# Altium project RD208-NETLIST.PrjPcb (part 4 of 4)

## Sheet 8.SchDoc
size 609 x 444 mm
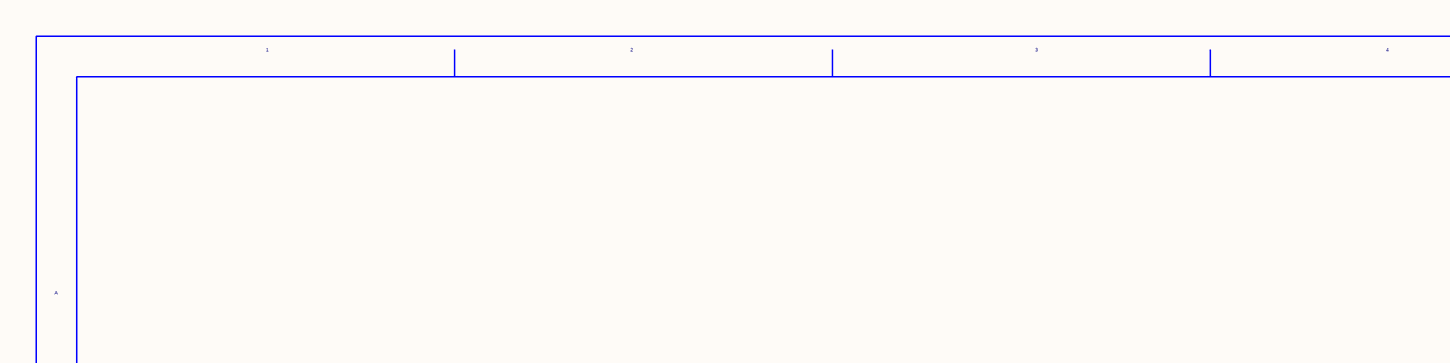
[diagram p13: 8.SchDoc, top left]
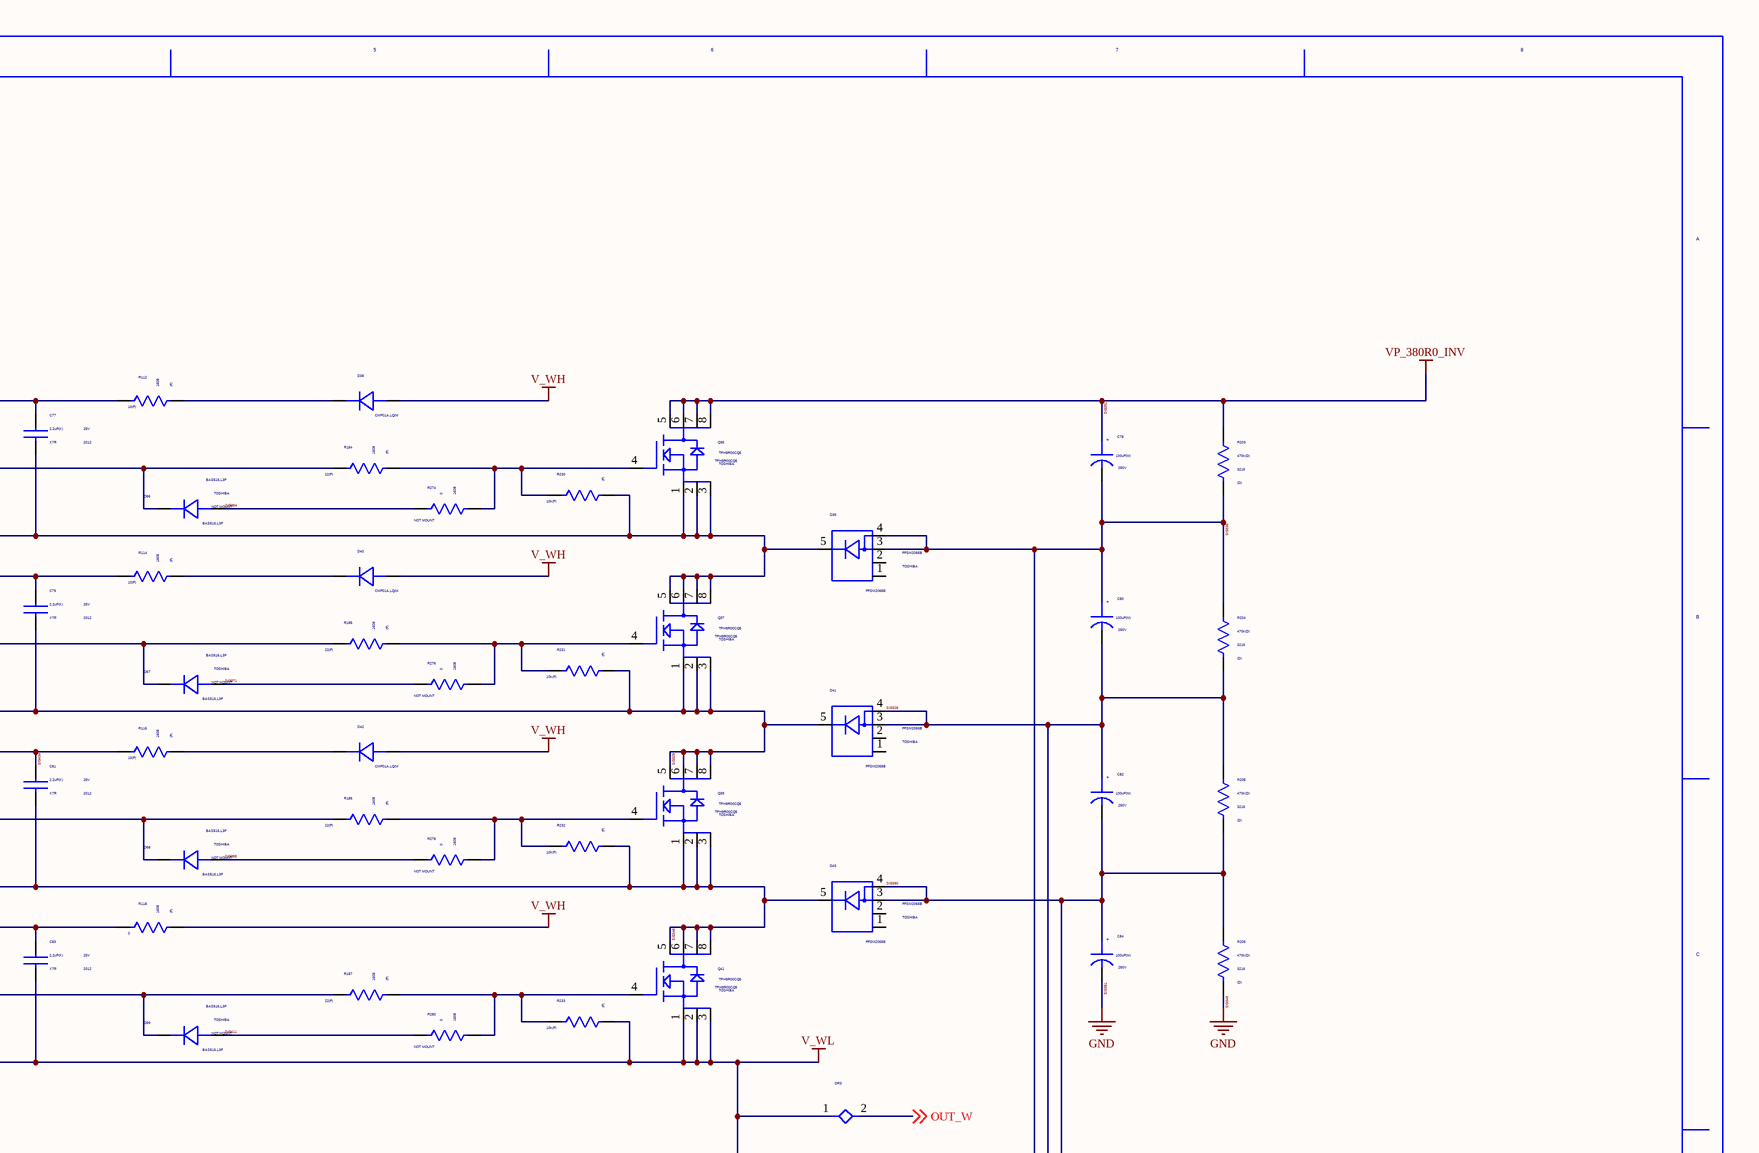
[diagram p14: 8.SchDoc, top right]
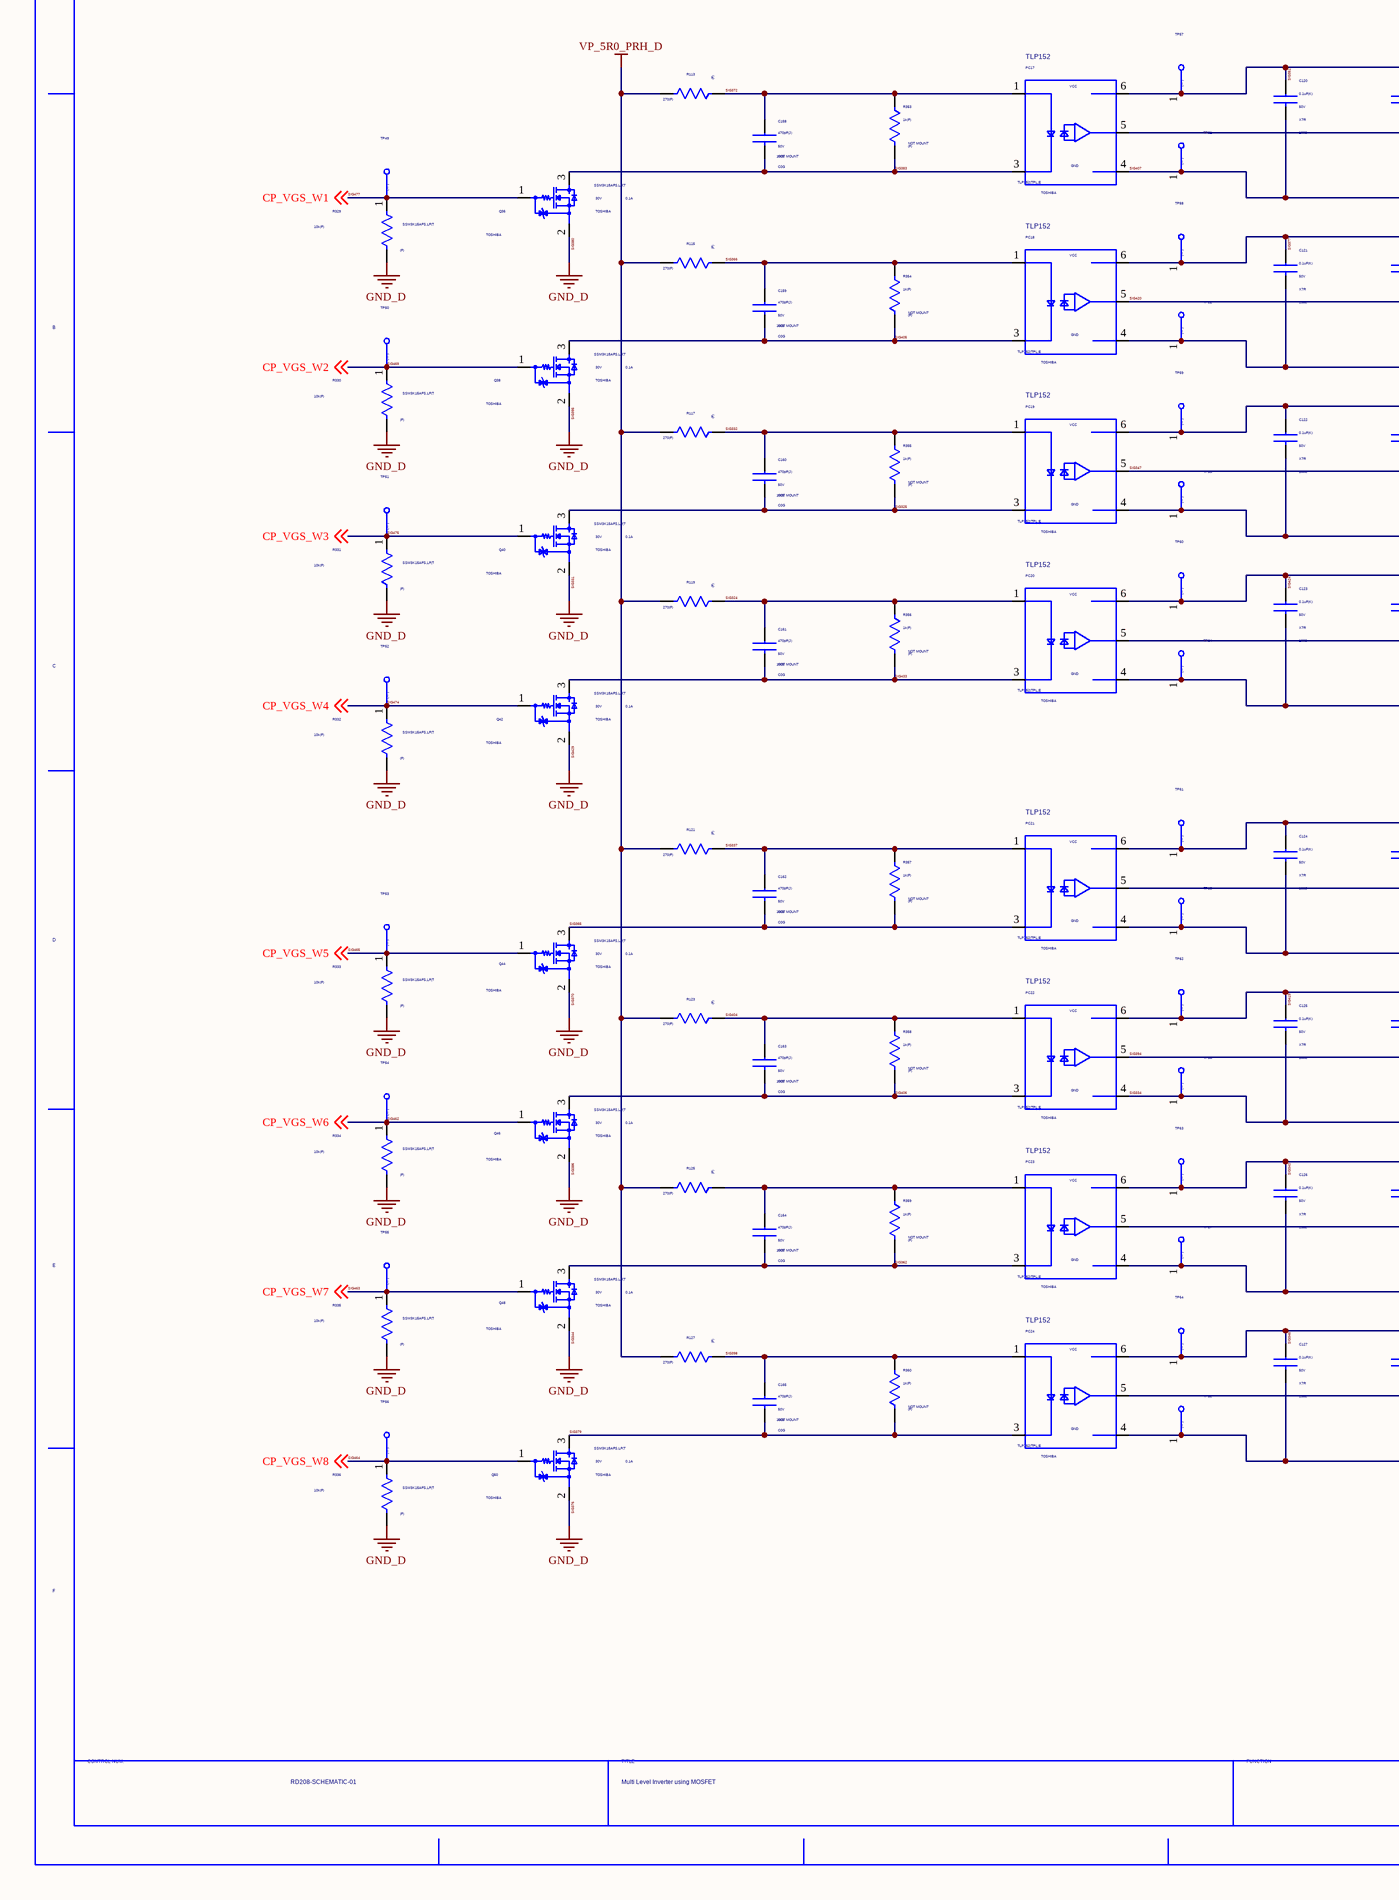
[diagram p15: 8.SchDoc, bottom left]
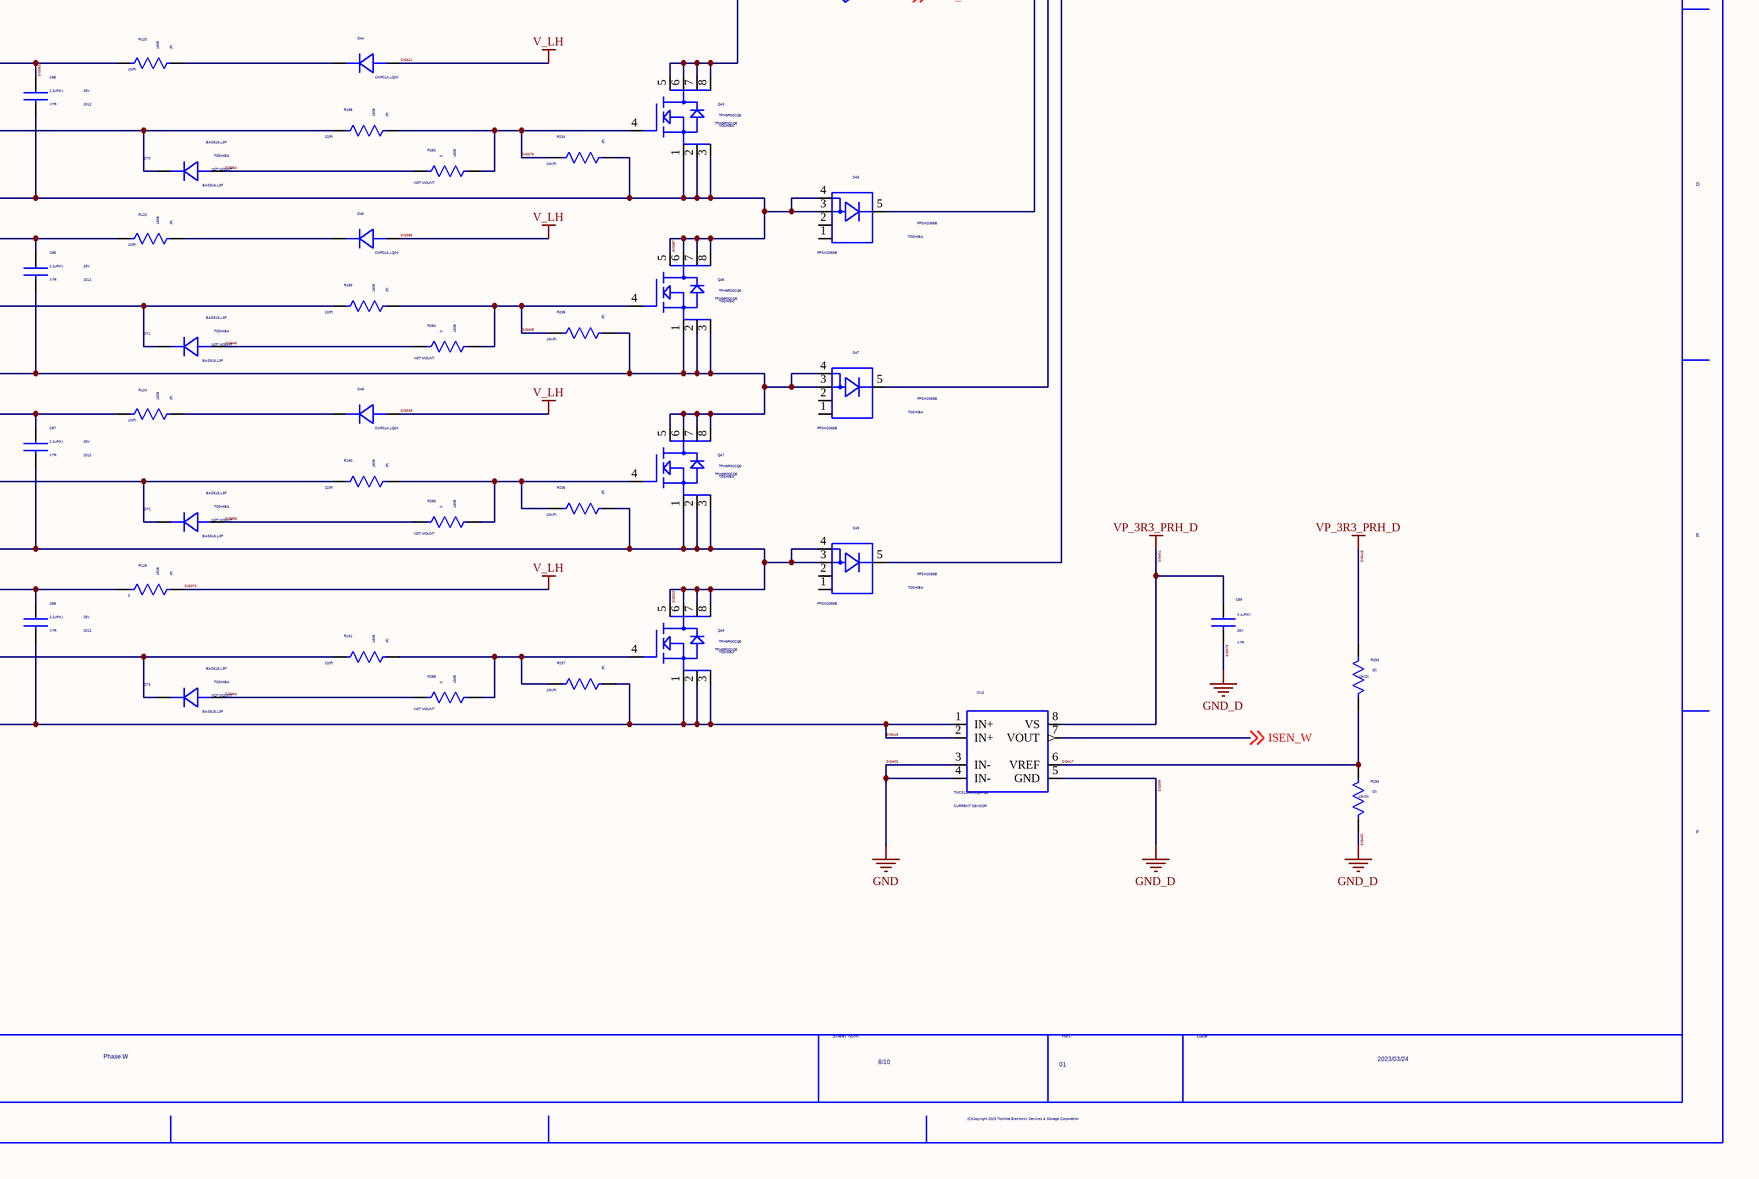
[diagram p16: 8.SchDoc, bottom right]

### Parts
(Parts that share a designator on the sheet are numbered #1, #2 ... from top to bottom, then left to right.)
C77  VAL2: 25V  SIZECODESMD: 2012  VALUE4: X7R  VAL1: 2.2uF(K)  (hidden comment: GRM21BR71E225KE11L)
C78  VAL2: 250V  VAL1: 100uF(M)  (hidden comment: EKMQ251ELL101ML25S)
C79  VAL2: 25V  SIZECODESMD: 2012  VALUE4: X7R  VAL1: 2.2uF(K)  (hidden comment: GRM21BR71E225KE11L)
C80  VAL2: 250V  VAL1: 100uF(M)  (hidden comment: EKMQ251ELL101ML25S)
C81  VAL2: 25V  SIZECODESMD: 2012  VALUE4: X7R  VAL1: 2.2uF(K)  (hidden comment: GRM21BR71E225KE11L)
C82  VAL2: 250V  VAL1: 100uF(M)  (hidden comment: EKMQ251ELL101ML25S)
C83  VAL2: 25V  SIZECODESMD: 2012  VALUE4: X7R  VAL1: 2.2uF(K)  (hidden comment: GRM21BR71E225KE11L)
C84  VAL2: 250V  VAL1: 100uF(M)  (hidden comment: EKMQ251ELL101ML25S)
C85  VAL2: 25V  SIZECODESMD: 2012  VALUE4: X7R  VAL1: 2.2uF(K)  (hidden comment: GRM21BR71E225KE11L)
C86  VAL2: 25V  SIZECODESMD: 2012  VALUE4: X7R  VAL1: 2.2uF(K)  (hidden comment: GRM21BR71E225KE11L)
C87  VAL2: 25V  SIZECODESMD: 2012  VALUE4: X7R  VAL1: 2.2uF(K)  (hidden comment: GRM21BR71E225KE11L)
C88  VAL2: 25V  SIZECODESMD: 2012  VALUE4: X7R  VAL1: 2.2uF(K)  (hidden comment: GRM21BR71E225KE11L)
C89  VAL2: 25V  VALUE4: X7R  VAL1: 0.1uF(K)  (hidden comment: GRM155R71E104KE14D)
C120  VAL2: 50V  SIZECODESMD: 1608  VALUE4: X7R  VAL1: 0.1uF(K)  (hidden comment: C1608X7R1H104K080AA)
C121  VAL2: 50V  SIZECODESMD: 1608  VALUE4: X7R  VAL1: 0.1uF(K)  (hidden comment: C1608X7R1H104K080AA)
C122  VAL2: 50V  SIZECODESMD: 1608  VALUE4: X7R  VAL1: 0.1uF(K)  (hidden comment: C1608X7R1H104K080AA)
C123  VAL2: 50V  SIZECODESMD: 1608  VALUE4: X7R  VAL1: 0.1uF(K)  (hidden comment: C1608X7R1H104K080AA)
C124  VAL2: 50V  SIZECODESMD: 1608  VALUE4: X7R  VAL1: 0.1uF(K)  (hidden comment: C1608X7R1H104K080AA)
C125  VAL2: 50V  SIZECODESMD: 1608  VALUE4: X7R  VAL1: 0.1uF(K)  (hidden comment: C1608X7R1H104K080AA)
C126  VAL2: 50V  SIZECODESMD: 1608  VALUE4: X7R  VAL1: 0.1uF(K)  (hidden comment: C1608X7R1H104K080AA)
C127  VAL2: 50V  SIZECODESMD: 1608  VALUE4: X7R  VAL1: 0.1uF(K)  (hidden comment: C1608X7R1H104K080AA)
C158  VAL2: 50V  SIZECODESMD: 1005  VALUE4: C0G  VAL1: 470pF(J)  NOTMOUNT: NOT MOUNT  (hidden comment: GRM1555C1H471JA01J)
C159  VAL2: 50V  SIZECODESMD: 1005  VALUE4: C0G  VAL1: 470pF(J)  NOTMOUNT: NOT MOUNT  (hidden comment: GRM1555C1H471JA01J)
C160  VAL2: 50V  SIZECODESMD: 1005  VALUE4: C0G  VAL1: 470pF(J)  NOTMOUNT: NOT MOUNT  (hidden comment: GRM1555C1H471JA01J)
C161  VAL2: 50V  SIZECODESMD: 1005  VALUE4: C0G  VAL1: 470pF(J)  NOTMOUNT: NOT MOUNT  (hidden comment: GRM1555C1H471JA01J)
C162  VAL2: 50V  SIZECODESMD: 1005  VALUE4: C0G  VAL1: 470pF(J)  NOTMOUNT: NOT MOUNT  (hidden comment: GRM1555C1H471JA01J)
C163  VAL2: 50V  SIZECODESMD: 1005  VALUE4: C0G  VAL1: 470pF(J)  NOTMOUNT: NOT MOUNT  (hidden comment: GRM1555C1H471JA01J)
C164  VAL2: 50V  SIZECODESMD: 1005  VALUE4: C0G  VAL1: 470pF(J)  NOTMOUNT: NOT MOUNT  (hidden comment: GRM1555C1H471JA01J)
C165  VAL2: 50V  SIZECODESMD: 1005  VALUE4: C0G  VAL1: 470pF(J)  NOTMOUNT: NOT MOUNT  (hidden comment: GRM1555C1H471JA01J)
D38  VAL1: CMF01A,LQ(M  (hidden comment: CMF01A,LQ_M)
D39  USERCOMPTEXT3: TOSHIBA  (hidden comment: FFSM2065B)
D40  VAL1: CMF01A,LQ(M  (hidden comment: CMF01A,LQ_M)
D41  USERCOMPTEXT3: TOSHIBA  (hidden comment: FFSM2065B)
D42  VAL1: CMF01A,LQ(M  (hidden comment: CMF01A,LQ_M)
D43  USERCOMPTEXT3: TOSHIBA  (hidden comment: FFSM2065B)
D44  VAL1: CMF01A,LQ(M  (hidden comment: CMF01A,LQ_M)
D45  USERCOMPTEXT3: TOSHIBA  (hidden comment: FFSM2065B)
D46  VAL1: CMF01A,LQ(M  (hidden comment: CMF01A,LQ_M)
D47  USERCOMPTEXT3: TOSHIBA  (hidden comment: FFSM2065B)
D48  VAL1: CMF01A,LQ(M  (hidden comment: CMF01A,LQ_M)
D49  USERCOMPTEXT3: TOSHIBA  (hidden comment: FFSM2065B)
D66  USERCOMPTEXT3: TOSHIBA  NOTMOUNT: NOT MOUNT  (hidden comment: BAS516,L3F)
D67  USERCOMPTEXT3: TOSHIBA  NOTMOUNT: NOT MOUNT  (hidden comment: BAS516,L3F)
D68  USERCOMPTEXT3: TOSHIBA  NOTMOUNT: NOT MOUNT  (hidden comment: BAS516,L3F)
D69  USERCOMPTEXT3: TOSHIBA  NOTMOUNT: NOT MOUNT  (hidden comment: BAS516,L3F)
D70  USERCOMPTEXT3: TOSHIBA  NOTMOUNT: NOT MOUNT  (hidden comment: BAS516,L3F)
D71  USERCOMPTEXT3: TOSHIBA  NOTMOUNT: NOT MOUNT  (hidden comment: BAS516,L3F)
D72  USERCOMPTEXT3: TOSHIBA  NOTMOUNT: NOT MOUNT  (hidden comment: BAS516,L3F)
D73  USERCOMPTEXT3: TOSHIBA  NOTMOUNT: NOT MOUNT  (hidden comment: BAS516,L3F)
DR3  STAR2  (value not drawn)
IC12  VAL2: CURRENT SENSOR  (hidden comment: TMCS1100A1QDRQ1)
PC17  SCH_NAME: TLP152  USERCOMPTEXT3: TOSHIBA  VAL3: TLP152(TPL,E  (hidden comment: TLP152_TPL,E)
PC18  SCH_NAME: TLP152  USERCOMPTEXT3: TOSHIBA  VAL3: TLP152(TPL,E  (hidden comment: TLP152_TPL,E)
PC19  SCH_NAME: TLP152  USERCOMPTEXT3: TOSHIBA  VAL3: TLP152(TPL,E  (hidden comment: TLP152_TPL,E)
PC20  SCH_NAME: TLP152  USERCOMPTEXT3: TOSHIBA  VAL3: TLP152(TPL,E  (hidden comment: TLP152_TPL,E)
PC21  SCH_NAME: TLP152  USERCOMPTEXT3: TOSHIBA  VAL3: TLP152(TPL,E  (hidden comment: TLP152_TPL,E)
PC22  SCH_NAME: TLP152  USERCOMPTEXT3: TOSHIBA  VAL3: TLP152(TPL,E  (hidden comment: TLP152_TPL,E)
PC23  SCH_NAME: TLP152  USERCOMPTEXT3: TOSHIBA  VAL3: TLP152(TPL,E  (hidden comment: TLP152_TPL,E)
PC24  SCH_NAME: TLP152  USERCOMPTEXT3: TOSHIBA  VAL3: TLP152(TPL,E  (hidden comment: TLP152_TPL,E)
Q35  USERCOMPTEXT3: TOSHIBA  (hidden comment: TPH9R00CQ5)
Q36  VAL2: 0.1A  MANUFACTURER: TOSHIBA  SIZECODESMD: 30V  VAL1: SSM3K15AFS,LF(T  (hidden comment: SSM3K15AFS,LF_T)
Q37  USERCOMPTEXT3: TOSHIBA  (hidden comment: TPH9R00CQ5)
Q38  VAL2: 0.1A  MANUFACTURER: TOSHIBA  SIZECODESMD: 30V  VAL1: SSM3K15AFS,LF(T  (hidden comment: SSM3K15AFS,LF_T)
Q39  USERCOMPTEXT3: TOSHIBA  (hidden comment: TPH9R00CQ5)
Q40  VAL2: 0.1A  MANUFACTURER: TOSHIBA  SIZECODESMD: 30V  VAL1: SSM3K15AFS,LF(T  (hidden comment: SSM3K15AFS,LF_T)
Q41  USERCOMPTEXT3: TOSHIBA  (hidden comment: TPH9R00CQ5)
Q42  VAL2: 0.1A  MANUFACTURER: TOSHIBA  SIZECODESMD: 30V  VAL1: SSM3K15AFS,LF(T  (hidden comment: SSM3K15AFS,LF_T)
Q43  USERCOMPTEXT3: TOSHIBA  (hidden comment: TPH9R00CQ5)
Q44  VAL2: 0.1A  MANUFACTURER: TOSHIBA  SIZECODESMD: 30V  VAL1: SSM3K15AFS,LF(T  (hidden comment: SSM3K15AFS,LF_T)
Q45  USERCOMPTEXT3: TOSHIBA  (hidden comment: TPH9R00CQ5)
Q46  VAL2: 0.1A  MANUFACTURER: TOSHIBA  SIZECODESMD: 30V  VAL1: SSM3K15AFS,LF(T  (hidden comment: SSM3K15AFS,LF_T)
Q47  USERCOMPTEXT3: TOSHIBA  (hidden comment: TPH9R00CQ5)
Q48  VAL2: 0.1A  MANUFACTURER: TOSHIBA  SIZECODESMD: 30V  VAL1: SSM3K15AFS,LF(T  (hidden comment: SSM3K15AFS,LF_T)
Q49  USERCOMPTEXT3: TOSHIBA  (hidden comment: TPH9R00CQ5)
Q50  VAL2: 0.1A  MANUFACTURER: TOSHIBA  SIZECODESMD: 30V  VAL1: SSM3K15AFS,LF(T  (hidden comment: SSM3K15AFS,LF_T)
R112  SIZECODESMD: 1608  VALUE4: (F)  VAL1: 10(F)  (hidden comment: ERJ3EKF10R0V)
R113  VALUE4: (F)  VAL1: 270(F)  (hidden comment: ERJ2RKF2700X)
R114  SIZECODESMD: 1608  VALUE4: (F)  VAL1: 10(F)  (hidden comment: ERJ3EKF10R0V)
R115  VALUE4: (F)  VAL1: 270(F)  (hidden comment: ERJ2RKF2700X)
R116  SIZECODESMD: 1608  VALUE4: (F)  VAL1: 10(F)  (hidden comment: ERJ3EKF10R0V)
R117  VALUE4: (F)  VAL1: 270(F)  (hidden comment: ERJ2RKF2700X)
R118  SIZECODESMD: 1608  VALUE4: (F)  VAL1: 0  (hidden comment: ERJ3EKF10R0V)
R119  VALUE4: (F)  VAL1: 270(F)  (hidden comment: ERJ2RKF2700X)
R120  SIZECODESMD: 1608  VALUE4: (F)  VAL1: 10(F)  (hidden comment: ERJ3EKF10R0V)
R121  VALUE4: (F)  VAL1: 270(F)  (hidden comment: ERJ2RKF2700X)
R122  SIZECODESMD: 1608  VALUE4: (F)  VAL1: 10(F)  (hidden comment: ERJ3EKF10R0V)
R123  VALUE4: (F)  VAL1: 270(F)  (hidden comment: ERJ2RKF2700X)
R124  SIZECODESMD: 1608  VALUE4: (F)  VAL1: 10(F)  (hidden comment: ERJ3EKF10R0V)
R125  VALUE4: (F)  VAL1: 270(F)  (hidden comment: ERJ2RKF2700X)
R126  SIZECODESMD: 1608  VALUE4: (F)  VAL1: 0  (hidden comment: ERJ3EKF10R0V)
R127  VALUE4: (F)  VAL1: 270(F)  (hidden comment: ERJ2RKF2700X)
R184  SIZECODESMD: 1608  VALUE4: (F)  VAL1: 22(F)  (hidden comment: ERJ3EKF22R0V)
R185  SIZECODESMD: 1608  VALUE4: (F)  VAL1: 22(F)  (hidden comment: ERJ3EKF22R0V)
R186  SIZECODESMD: 1608  VALUE4: (F)  VAL1: 22(F)  (hidden comment: ERJ3EKF22R0V)
R187  SIZECODESMD: 1608  VALUE4: (F)  VAL1: 22(F)  (hidden comment: ERJ3EKF22R0V)
R188  SIZECODESMD: 1608  VALUE4: (F)  VAL1: 22(F)  (hidden comment: ERJ3EKF22R0V)
R189  SIZECODESMD: 1608  VALUE4: (F)  VAL1: 22(F)  (hidden comment: ERJ3EKF22R0V)
R190  SIZECODESMD: 1608  VALUE4: (F)  VAL1: 22(F)  (hidden comment: ERJ3EKF22R0V)
R191  SIZECODESMD: 1608  VALUE4: (F)  VAL1: 22(F)  (hidden comment: ERJ3EKF22R0V)
R203  SIZECODESMD: 3216  VALUE4: (D)  VAL1: 470k(D)  (hidden comment: HV73V2BTTD4703D)
R204  SIZECODESMD: 3216  VALUE4: (D)  VAL1: 470k(D)  (hidden comment: HV73V2BTTD4703D)
R205  SIZECODESMD: 3216  VALUE4: (D)  VAL1: 470k(D)  (hidden comment: HV73V2BTTD4703D)
R206  SIZECODESMD: 3216  VALUE4: (D)  VAL1: 470k(D)  (hidden comment: HV73V2BTTD4703D)
R230  VALUE4: (F)  VAL1: 10k(F)  (hidden comment: ERJ2RKF1002X)
R231  VALUE4: (F)  VAL1: 10k(F)  (hidden comment: ERJ2RKF1002X)
R232  VALUE4: (F)  VAL1: 10k(F)  (hidden comment: ERJ2RKF1002X)
R233  VALUE4: (F)  VAL1: 10k(F)  (hidden comment: ERJ2RKF1002X)
R234  VALUE4: (F)  VAL1: 10k(F)  (hidden comment: ERJ2RKF1002X)
R235  VALUE4: (F)  VAL1: 10k(F)  (hidden comment: ERJ2RKF1002X)
R236  VALUE4: (F)  VAL1: 10k(F)  (hidden comment: ERJ2RKF1002X)
R237  VALUE4: (F)  VAL1: 10k(F)  (hidden comment: ERJ2RKF1002X)
R274  SIZECODESMD: 1608  VAL1: 0  NOTMOUNT: NOT MOUNT  (hidden comment: ERJ3GEY0R00V)
R276  SIZECODESMD: 1608  VAL1: 0  NOTMOUNT: NOT MOUNT  (hidden comment: ERJ3GEY0R00V)
R278  SIZECODESMD: 1608  VAL1: 0  NOTMOUNT: NOT MOUNT  (hidden comment: ERJ3GEY0R00V)
R280  SIZECODESMD: 1608  VAL1: 0  NOTMOUNT: NOT MOUNT  (hidden comment: ERJ3GEY0R00V)
R282  SIZECODESMD: 1608  VAL1: 0  NOTMOUNT: NOT MOUNT  (hidden comment: ERJ3GEY0R00V)
R284  SIZECODESMD: 1608  VAL1: 0  NOTMOUNT: NOT MOUNT  (hidden comment: ERJ3GEY0R00V)
R286  SIZECODESMD: 1608  VAL1: 0  NOTMOUNT: NOT MOUNT  (hidden comment: ERJ3GEY0R00V)
R288  SIZECODESMD: 1608  VAL1: 0  NOTMOUNT: NOT MOUNT  (hidden comment: ERJ3GEY0R00V)
R293  VALUE4: (D)  VAL1: 10k(D)  (hidden comment: RK73G1ETTP1002D)
R294  VALUE4: (D)  VAL1: 10k(D)  (hidden comment: RK73G1ETTP1002D)
R329  VALUE4: (F)  VAL1: 10k(F)  (hidden comment: ERJ2RKF1002X)
R330  VALUE4: (F)  VAL1: 10k(F)  (hidden comment: ERJ2RKF1002X)
R331  VALUE4: (F)  VAL1: 10k(F)  (hidden comment: ERJ2RKF1002X)
R332  VALUE4: (F)  VAL1: 10k(F)  (hidden comment: ERJ2RKF1002X)
R333  VALUE4: (F)  VAL1: 10k(F)  (hidden comment: ERJ2RKF1002X)
R334  VALUE4: (F)  VAL1: 10k(F)  (hidden comment: ERJ2RKF1002X)
R335  VALUE4: (F)  VAL1: 10k(F)  (hidden comment: ERJ2RKF1002X)
R336  VALUE4: (F)  VAL1: 10k(F)  (hidden comment: ERJ2RKF1002X)
R353  VALUE4: (F)  VAL1: 1k(F)  NOTMOUNT: NOT MOUNT  (hidden comment: ERJ2RKF1001X)
R354  VALUE4: (F)  VAL1: 1k(F)  NOTMOUNT: NOT MOUNT  (hidden comment: ERJ2RKF1001X)
R355  VALUE4: (F)  VAL1: 1k(F)  NOTMOUNT: NOT MOUNT  (hidden comment: ERJ2RKF1001X)
R356  VALUE4: (F)  VAL1: 1k(F)  NOTMOUNT: NOT MOUNT  (hidden comment: ERJ2RKF1001X)
R357  VALUE4: (F)  VAL1: 1k(F)  NOTMOUNT: NOT MOUNT  (hidden comment: ERJ2RKF1001X)
R358  VALUE4: (F)  VAL1: 1k(F)  NOTMOUNT: NOT MOUNT  (hidden comment: ERJ2RKF1001X)
R359  VALUE4: (F)  VAL1: 1k(F)  NOTMOUNT: NOT MOUNT  (hidden comment: ERJ2RKF1001X)
R360  VALUE4: (F)  VAL1: 1k(F)  NOTMOUNT: NOT MOUNT  (hidden comment: ERJ2RKF1001X)
TP49  TP  (value not drawn)
TP50  TP  (value not drawn)
TP51  TP  (value not drawn)
TP52  TP  (value not drawn)
TP53  TP  (value not drawn)
TP54  TP  (value not drawn)
TP55  TP  (value not drawn)
TP56  TP  (value not drawn)
TP57  TP  (value not drawn)
TP58  TP  (value not drawn)
TP59  TP  (value not drawn)
TP60  TP  (value not drawn)
TP61  TP  (value not drawn)
TP62  TP  (value not drawn)
TP63  TP  (value not drawn)
TP64  TP  (value not drawn)
TP81  TP  (value not drawn)
TP82  TP  (value not drawn)
TP83  TP  (value not drawn)
TP84  TP  (value not drawn)
TP85  TP  (value not drawn)
TP86  TP  (value not drawn)
TP87  TP  (value not drawn)
TP88  TP  (value not drawn)
U?#8  DATE: 2023/03/24  TITLE: Multi Level Inverter using MOSFET  REVISION: 01  SHEETNUMBER: 8/10  DRAWINGNUMBER: RD208-SCHEMATIC-01  FUNCTION: Phase W  (hidden comment: WAKU_DEF_A3)

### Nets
GND: C84.2 IC12.3(IN-) IC12.4(IN-) R206.2  [also labelled SIG349, SIG381, SIG402]  [project net SIG200]
GND_D: C89.2 IC12.5(GND) Q36.2(E) Q38.2(E) Q40.2(E) Q42.2(E) Q44.2(E) Q46.2(E) Q48.2(E) Q50.2(E) R294.1 R329.2 R330.2 R331.2 R332.2 R333.2 R334.2 R335.2 R336.2  [also labelled SIG331, SIG344, SIG370, SIG376, SIG378, SIG380, SIG386, SIG395, SIG399, SIG429, SIG430]  [project net SIG10]
SIG339: D44.A(ANODE) D46.A(ANODE) D48.A(ANODE) R126.2  [also labelled SIG373, SIG388, SIG421, V_LH]  [project net SIG235]
SIG391: C78.1 Q35.5(D1) Q35.6(D2) Q35.7(D3) Q35.8(D4) R203.1  [also labelled VP_380R0_INV]  [project net SIG1]
SIG401: C89.1 IC12.8(VS) R293.2  [also labelled SIG415, VP_3R3_PRH_D]  [project net SIG107]
V_WH: D38.A(ANODE) D40.A(ANODE) D42.A(ANODE) R118.2
V_WL: C83.2 C123.2 DR3.1 PC20.4 Q41.1(S1) Q41.2(S2) Q41.3(S3) Q43.5(D1) Q43.6(D2) Q43.7(D3) Q43.8(D4) R233.2 TP84.1
VP_5R0_PRH_D: R113.1 R115.1 R117.1 R119.1 R121.1 R123.1 R125.1 R127.1  [project net SIG104]
ISEN_W: IC12.7(VOUT) ; off-sheet ISEN_W
OUT_W: DR3.2 ; off-sheet OUT_W
SIG324: C161.1 PC20.1 R119.2 R356.1
SIG325: C160.2 PC19.3 Q40.3(C) R355.2
SIG326: D42.K(CATHODE) R116.2
SIG327: D70.K(CATHODE) PC21.5 R188.1
SIG328: C80.2 C82.1 D41.3(ANODE3) D41.4(ANODE4) D47.5(CATHODE) R204.2 R205.1
SIG329: C79.2 C121.2 D41.5(CATHODE) PC18.4 Q37.1(S1) Q37.2(S2) Q37.3(S3) Q39.5(D1) Q39.6(D2) Q39.7(D3) Q39.8(D4) R231.2 TP82.1
SIG332: C160.1 PC19.1 R117.2 R355.1
SIG333: C87.2 C126.2 D49.3(ANODE3) D49.4(ANODE4) PC23.4 Q47.1(S1) Q47.2(S2) Q47.3(S3) Q49.5(D1) Q49.6(D2) Q49.7(D3) Q49.8(D4) R236.2 TP87.1
SIG334: C86.2 C125.2 D47.3(ANODE3) D47.4(ANODE4) PC22.4 Q45.1(S1) Q45.2(S2) Q45.3(S3) Q47.5(D1) Q47.6(D2) Q47.7(D3) Q47.8(D4) R235.2 TP86.1
SIG336: C78.2 C80.1 D39.3(ANODE3) D39.4(ANODE4) D45.5(CATHODE) R203.2 R204.1
SIG337: C162.1 PC21.1 R121.2 R357.1
SIG338: C164.1 PC23.1 R125.2 R359.1
SIG340: Q47.4(G) R190.2 R236.1 R286.2
SIG343: C87.1 C126.1 PC23.6 R124.1 TP63.1
SIG345: D71.A(ANODE) R284.1
SIG346: C88.1 C127.1 PC24.6 R126.1 TP64.1
SIG347: D68.K(CATHODE) PC19.5 R186.1
SIG348: C81.2 C122.2 D43.5(CATHODE) PC19.4 Q39.1(S1) Q39.2(S2) Q39.3(S3) Q41.5(D1) Q41.6(D2) Q41.7(D3) Q41.8(D4) R232.2 TP83.1
SIG350: D38.K(CATHODE) R112.2
SIG351: C77.1 C120.1 PC17.6 R112.1 TP57.1
SIG352: Q35.4(G) R184.2 R230.1 R274.2
SIG353: D44.K(CATHODE) R120.2
SIG354: D70.A(ANODE) R282.1
SIG355: D68.A(ANODE) R278.1
SIG356: D72.A(ANODE) R286.1
SIG362: C164.2 PC23.3 Q48.3(C) R359.2
SIG363: C85.1 C124.1 PC21.6 R120.1 TP61.1
SIG364: D73.A(ANODE) R288.1
SIG365: C162.2 PC21.3 Q44.3(C) R357.2
SIG366: C159.1 PC18.1 R115.2 R354.1
SIG367: D66.K(CATHODE) PC17.5 R184.1
SIG371: D67.A(ANODE) R276.1
SIG372: C158.1 PC17.1 R113.2 R353.1
SIG374: D73.K(CATHODE) PC24.5 R191.1
SIG375: Q43.4(G) R188.2 R234.1 R282.2
SIG377: C79.1 C121.1 PC18.6 R114.1 TP58.1
SIG379: C165.2 PC24.3 Q50.3(C) R360.2
SIG382: Q49.4(G) R191.2 R237.1 R288.2
SIG383: C158.2 PC17.3 Q36.3(C) R353.2
SIG384: D66.A(ANODE) R274.1
SIG387: C85.2 C124.2 D45.3(ANODE3) D45.4(ANODE4) PC21.4 Q43.1(S1) Q43.2(S2) Q43.3(S3) Q45.5(D1) Q45.6(D2) Q45.7(D3) Q45.8(D4) R234.2 TP85.1
SIG389: D48.K(CATHODE) R124.2
SIG390: C82.2 C84.1 D43.3(ANODE3) D43.4(ANODE4) D49.5(CATHODE) R205.2 R206.1
SIG394: D71.K(CATHODE) PC22.5 R189.1
SIG398: C165.1 PC24.1 R127.2 R360.1
SIG403: D69.K(CATHODE) PC20.5 R187.1
SIG404: C163.1 PC22.1 R123.2 R358.1
SIG405: C159.2 PC18.3 Q38.3(C) R354.2
SIG406: C163.2 PC22.3 Q46.3(C) R358.2
SIG407: C77.2 C120.2 D39.5(CATHODE) PC17.4 Q35.1(S1) Q35.2(S2) Q35.3(S3) Q37.5(D1) Q37.6(D2) Q37.7(D3) Q37.8(D4) R230.2 TP81.1
SIG408: Q45.4(G) R189.2 R235.1 R284.2
SIG409: Q37.4(G) R185.2 R231.1 R276.2
SIG410: Q39.4(G) R186.2 R232.1 R278.2
SIG411: D69.A(ANODE) R280.1
SIG413: D40.K(CATHODE) R114.2
SIG417: IC12.6(VREF) R293.1 R294.2
SIG418: C88.2 C127.2 IC12.1(IN+) IC12.2(IN+) PC24.4 Q49.1(S1) Q49.2(S2) Q49.3(S3) R237.2 TP88.1
SIG419: C86.1 C125.1 PC22.6 R122.1 TP62.1
SIG420: D67.K(CATHODE) PC18.5 R185.1
SIG423: D72.K(CATHODE) PC23.5 R190.1
SIG424: C83.1 C123.1 PC20.6 R118.1 TP60.1
SIG425: D46.K(CATHODE) R122.2
SIG426: Q41.4(G) R187.2 R233.1 R280.2
SIG433: C161.2 PC20.3 Q42.3(C) R356.2
SIG434: C81.1 C122.1 PC19.6 R116.1 TP59.1
SIG462: Q46.1(B) R334.1 TP54.1 ; off-sheet CP_VGS_W6  [also labelled CP_VGS_W6]
SIG463: Q48.1(B) R335.1 TP55.1 ; off-sheet CP_VGS_W7  [also labelled CP_VGS_W7]
SIG464: Q50.1(B) R336.1 TP56.1 ; off-sheet CP_VGS_W8  [also labelled CP_VGS_W8]
SIG465: Q44.1(B) R333.1 TP53.1 ; off-sheet CP_VGS_W5  [also labelled CP_VGS_W5]
SIG469: Q38.1(B) R330.1 TP50.1 ; off-sheet CP_VGS_W2  [also labelled CP_VGS_W2]
SIG474: Q42.1(B) R332.1 TP52.1 ; off-sheet CP_VGS_W4  [also labelled CP_VGS_W4]
SIG475: Q40.1(B) R331.1 TP51.1 ; off-sheet CP_VGS_W3  [also labelled CP_VGS_W3]
SIG477: Q36.1(B) R329.1 TP49.1 ; off-sheet CP_VGS_W1  [also labelled CP_VGS_W1]

Not connected (* = marked no-connect by the designer): D39 1(NC1) 2(NC2); D41 1(NC1) 2(NC2); D43 1(NC1) 2(NC2); D45 1(NC1) 2(NC2); D47 1(NC1) 2(NC2); D49 1(NC1) 2(NC2)

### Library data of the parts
C77 C79 C81 C83 C85-C88 = GRM21BR71E225KE11L: MANUFACTURER: MURATA; ITEM: CAP Ceramic; TIME: 08:44:45; UPDATEUSER: t5459927; SAVECOUNT: 1; OriginalSymbolOrigin: (0,0); INSTANCENAME: INS15860000
C78 = EKMQ251ELL101ML25S: MANUFACTURER: Nippon Chemi-Con; ITEM: CAP ALUM; TIME: 08:44:45; UPDATEUSER: t5459927; SAVECOUNT: 1; OriginalSymbolOrigin: (0,2540); INSTANCENAME: INS16070082
C80 = EKMQ251ELL101ML25S: MANUFACTURER: Nippon Chemi-Con; ITEM: CAP ALUM; TIME: 08:44:45; UPDATEUSER: t5459927; SAVECOUNT: 1; OriginalSymbolOrigin: (0,2540); INSTANCENAME: INS16070102
C82 = EKMQ251ELL101ML25S: MANUFACTURER: Nippon Chemi-Con; ITEM: CAP ALUM; TIME: 08:44:45; UPDATEUSER: t5459927; SAVECOUNT: 1; OriginalSymbolOrigin: (0,2540); INSTANCENAME: INS16070122
C84 = EKMQ251ELL101ML25S: MANUFACTURER: Nippon Chemi-Con; ITEM: CAP ALUM; TIME: 08:44:45; UPDATEUSER: t5459927; SAVECOUNT: 1; OriginalSymbolOrigin: (0,2540); INSTANCENAME: INS16070142
C89 = GRM155R71E104KE14D: MANUFACTURER: MURATA; ITEM: CAP Ceramic; SIZECODESMD: 1005; TIME: 08:44:45; UPDATEUSER: t5459927; SAVECOUNT: 1; OriginalSymbolOrigin: (0,0); INSTANCENAME: INS16776295
C120-C127 = C1608X7R1H104K080AA: MANUFACTURER: TDK; ITEM: CAP Ceramic; TIME: 08:44:45; UPDATEUSER: t5459927; SAVECOUNT: 1; OriginalSymbolOrigin: (0,0); INSTANCENAME: INS16097035
C158-C165 = GRM1555C1H471JA01J: MANUFACTURER: MURATA; ITEM: CAP Ceramic; TIME: 08:44:46; UPDATEUSER: t5459927; SAVECOUNT: 1; OriginalSymbolOrigin: (0,0); INSTANCENAME: INS17224098
D38 D40 D42 D44 D46 D48 = CMF01A,LQ_M: MANUFACTURER: TOSHIBA; COMP: CMF01A_LQ_M; ITEM: DIODE; TIME: 08:44:46; UPDATEUSER: t5459927; SAVECOUNT: 1; OriginalSymbolOrigin: (0,0); INSTANCENAME: INS15860772
D39 D41 D43 D45 D47 D49 = FFSM2065B: MANUFACTURER: ON_SEMI; ITEM: DIODE; TIME: 08:44:45; UPDATEUSER: t5459927; SAVECOUNT: 1; SAVEAREA0: -3235,-11101,10576,-990; OriginalSymbolOrigin: (0,0); INSTANCENAME: INS16711377
D66-D73 = BAS516,L3F: COMP: BAS516_L3F; ITEM: DIODE; TIME: 08:44:45; UPDATEUSER: t5459927; SAVECOUNT: 1; OriginalSymbolOrigin: (0,0); INSTANCENAME: INS16674713
DR3 = STAR2: TIME: 12:37:47; UPDATEUSER: d5009410; UPDATETIME: 12:51:51; SAVECOUNT: 17; SAVEAREA0: -6564,-5245,9999,5672; OriginalSymbolOrigin: (-2540,2540); COMP: ONEPOINT
IC12 = TMCS1100A1QDRQ1: MANUFACTURER: TI; ITEM: IC CurrentSensor; TIME: 08:44:45; UPDATEUSER: PS4_common_PC; UPDATETIME: 16:01:14; SAVECOUNT: 3; SAVEAREA0: -10605,-15555,25377,840; OriginalSymbolOrigin: (0,0)
PC17-PC24 = TLP152_TPL,E: ITEM: Photocoupler; COMP: TLP152_TPL_E; TIME: 08:44:45; UPDATEUSER: t5459927; SAVECOUNT: 1; OriginalSymbolOrigin: (0,0); INSTANCENAME: INS15861608
Q35 Q37 Q39 Q41 Q43 Q45 Q47 Q49 = TPH9R00CQ5: ITEM: FET; ORDER: 0; TIME: 08:44:45; UPDATEUSER: t5459927; SAVECOUNT: 1; OriginalSymbolOrigin: (0,0); INSTANCENAME: INS15860992
Q36 Q38 Q40 Q42 Q44 Q46 Q48 Q50 = SSM3K15AFS,LF_T: ITEM: Digital Transistor NPN; COMP: SSM3K15AFS-123; ORDER: 0; TIME: 08:44:45; UPDATEUSER: t5459927; SAVECOUNT: 1; OriginalSymbolOrigin: (0,0); INSTANCENAME: INS15859756
R112 R114 R116 R120 R122 R124 = ERJ3EKF10R0V: MANUFACTURER: Panasonic; ITEM: Register; VAL2: 100mW; TIME: 08:44:45; UPDATEUSER: t5459927; SAVECOUNT: 1; OriginalSymbolOrigin: (0,0); INSTANCENAME: INS16646496
R113 R115 R117 R119 R121 R123 R125 R127 = ERJ2RKF2700X: MANUFACTURER: Panasonic; ITEM: Register; VAL2: 100mW; SIZECODESMD: 1005; TIME: 08:44:45; UPDATEUSER: t5459927; SAVECOUNT: 1; OriginalSymbolOrigin: (0,0); INSTANCENAME: INS16151457
R118 R126 = ERJ3EKF10R0V: MANUFACTURER: Panasonic; ITEM: Register; VAL2: 1/10W; COMP: ERJ3GEY0R00V; TIME: 08:44:45; UPDATEUSER: t5459927; SAVECOUNT: 1; OriginalSymbolOrigin: (0,0); INSTANCENAME: INS16646496
R184-R191 = ERJ3EKF22R0V: MANUFACTURER: Panasonic; ITEM: Register; VAL2: 100mW; TIME: 08:44:45; UPDATEUSER: t5459927; SAVECOUNT: 1; OriginalSymbolOrigin: (0,0); INSTANCENAME: INS17210794
R203 = HV73V2BTTD4703D: MANUFACTURER: KOA; ITEM: Register; VAL2: 0.33W; TIME: 08:44:45; UPDATEUSER: t5459927; SAVECOUNT: 1; OriginalSymbolOrigin: (0,0); INSTANCENAME: INS16806843
R204 = HV73V2BTTD4703D: MANUFACTURER: KOA; ITEM: Register; VAL2: 0.33W; TIME: 08:44:45; UPDATEUSER: t5459927; SAVECOUNT: 1; OriginalSymbolOrigin: (0,0); INSTANCENAME: INS16806859
R205 = HV73V2BTTD4703D: MANUFACTURER: KOA; ITEM: Register; VAL2: 0.33W; TIME: 08:44:45; UPDATEUSER: t5459927; SAVECOUNT: 1; OriginalSymbolOrigin: (0,0); INSTANCENAME: INS16806875
R206 = HV73V2BTTD4703D: MANUFACTURER: KOA; ITEM: Register; VAL2: 0.33W; TIME: 08:44:45; UPDATEUSER: t5459927; SAVECOUNT: 1; OriginalSymbolOrigin: (0,0); INSTANCENAME: INS16806891
R230-R237 = ERJ2RKF1002X: MANUFACTURER: Panasonic; ITEM: Register; VAL2: 100mW; SIZECODESMD: 1005; TIME: 08:44:45; UPDATEUSER: t5459927; SAVECOUNT: 1; OriginalSymbolOrigin: (0,0); INSTANCENAME: INS16648754
R274 R276 R278 R280 R282 R284 R286 R288 = ERJ3GEY0R00V: MANUFACTURER: Panasonic; ITEM: Register; VAL2: 1/10W; TIME: 08:44:45; UPDATEUSER: t5459927; SAVECOUNT: 1; OriginalSymbolOrigin: (0,0); INSTANCENAME: INS16674743
R293 = RK73G1ETTP1002D: MANUFACTURER: KOA; ITEM: Register; VAL2: 100mW; SIZECODESMD: 1005; TIME: 08:44:46; UPDATEUSER: t5459927; SAVECOUNT: 1; OriginalSymbolOrigin: (0,0); INSTANCENAME: INS16808670
R294 = RK73G1ETTP1002D: MANUFACTURER: KOA; ITEM: Register; VAL2: 100mW; SIZECODESMD: 1005; TIME: 08:44:46; UPDATEUSER: t5459927; SAVECOUNT: 1; OriginalSymbolOrigin: (0,0); INSTANCENAME: INS16808683
R329-R336 = ERJ2RKF1002X: MANUFACTURER: Panasonic; ITEM: Register; VAL2: 100mW; SIZECODESMD: 1005; TIME: 08:44:45; UPDATEUSER: t5459927; SAVECOUNT: 1; OriginalSymbolOrigin: (0,0); INSTANCENAME: INS17222356
R353-R360 = ERJ2RKF1001X: MANUFACTURER: Panasonic; ITEM: Register; VAL2: 100mW; SIZECODESMD: 1005; TIME: 08:44:45; UPDATEUSER: t5459927; SAVECOUNT: 1; OriginalSymbolOrigin: (0,0); INSTANCENAME: INS17224061
TP49-TP64 TP81-TP88 = TP: TIME: 16:12:21; UPDATEUSER: fukuda-y; UPDATETIME: 16:18:11; SAVECOUNT: 2; SAVEAREA0: -242,-92,12810,7836; OriginalSymbolOrigin: (0,7620); VAL3: TH Hole dia. 1.0; COMP: TP-TH1.0-L1.6
U?#8 = WAKU_DEF_A3: PLOTTIME: HH:MM; SAVEAREA0: -311037,-554865,914355,115662; TIME: 14:30:25; UPDATEUSER: PS4_common_PC; UPDATETIME: 08:25:56; SAVECOUNT: 18; ZONEOFFSETX: 36; ZONEOFFSETY: -24; OriginalSymbolOrigin: (12700,-12700)

## Sheet 9.SchDoc
size 420 x 297 mm
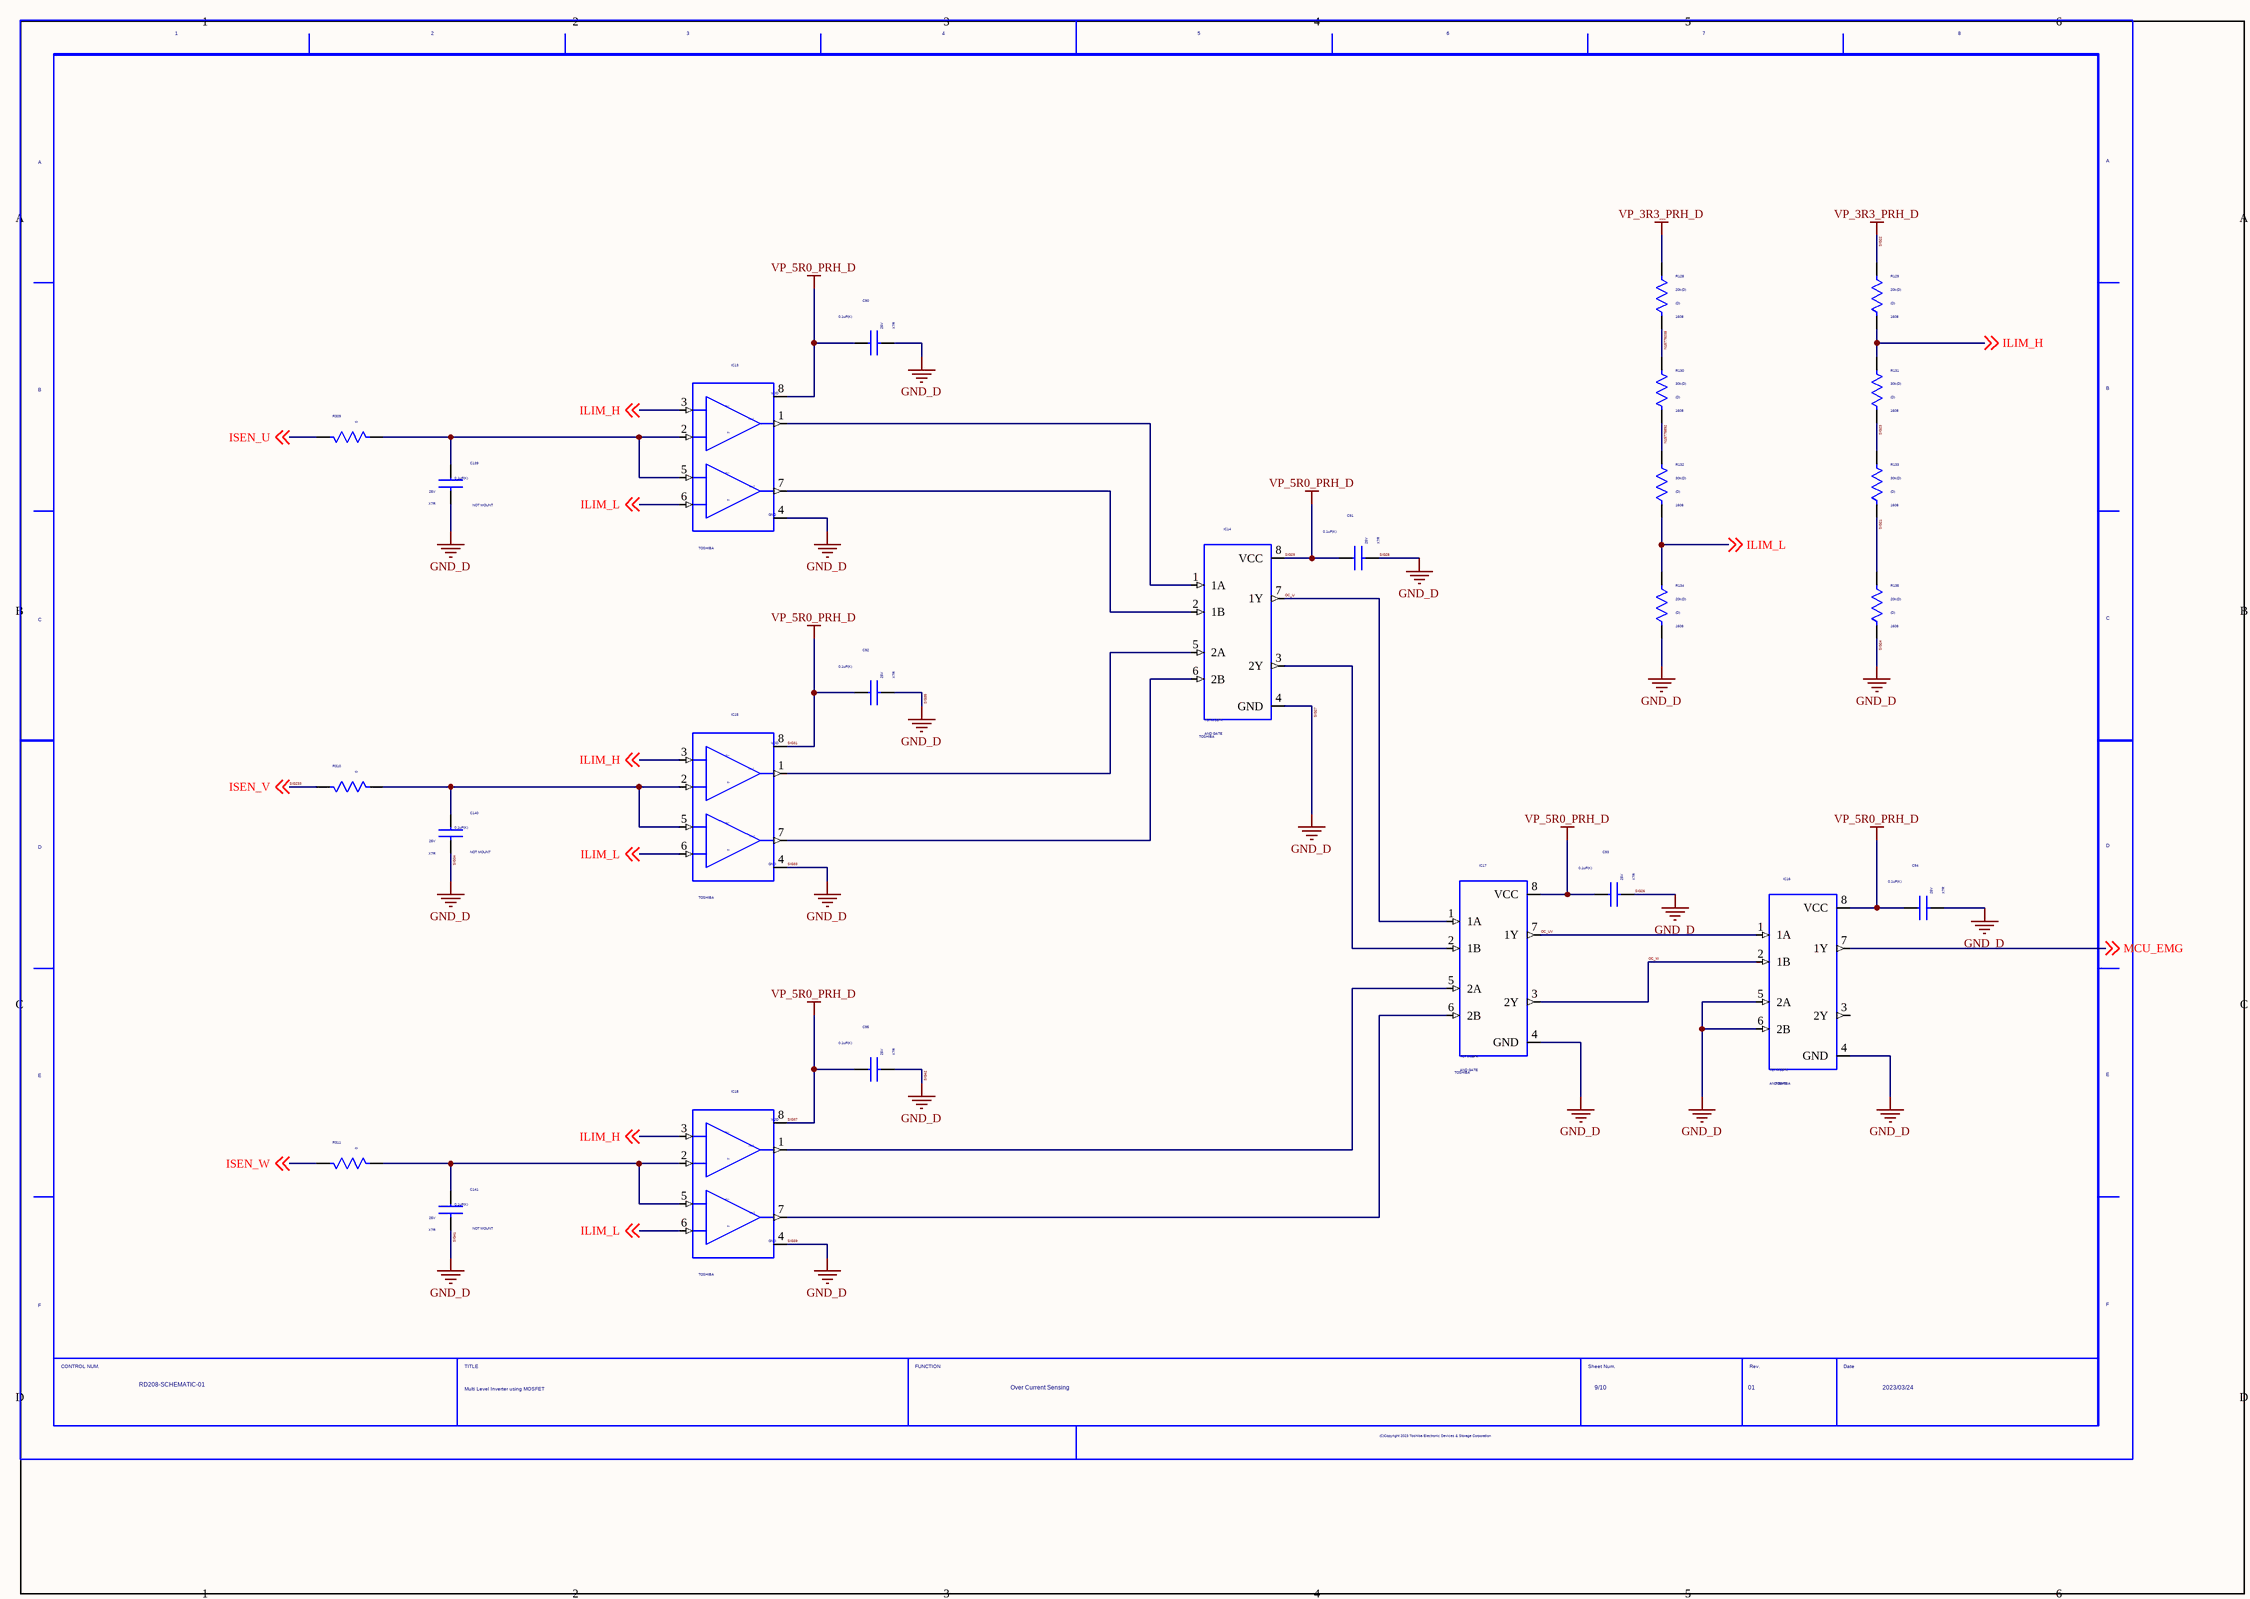
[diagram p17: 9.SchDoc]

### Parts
(Parts that share a designator on the sheet are numbered #1, #2 ... from top to bottom, then left to right.)
C90  VAL2: 25V  VALUE4: X7R  VAL1: 0.1uF(K)  (hidden comment: GRM155R71E104KE14D)
C91  VAL2: 25V  VALUE4: X7R  VAL1: 0.1uF(K)  (hidden comment: GRM155R71E104KE14D)
C92  VAL2: 25V  VALUE4: X7R  VAL1: 0.1uF(K)  (hidden comment: GRM155R71E104KE14D)
C93  VAL2: 25V  VALUE4: X7R  VAL1: 0.1uF(K)  (hidden comment: GRM155R71E104KE14D)
C94  VAL2: 25V  VALUE4: X7R  VAL1: 0.1uF(K)  (hidden comment: GRM155R71E104KE14D)
C95  VAL2: 25V  VALUE4: X7R  VAL1: 0.1uF(K)  (hidden comment: GRM155R71E104KE14D)
C139  VAL2: 25V  VALUE4: X7R  VAL1: 0.1uF(K)  NOTMOUNT: NOT MOUNT  (hidden comment: GRM155R71E104KE14D)
C140  VAL2: 25V  VALUE4: X7R  VAL1: 0.1uF(K)  NOTMOUNT: NOT MOUNT  (hidden comment: GRM155R71E104KE14D)
C141  VAL2: 25V  VALUE4: X7R  VAL1: 0.1uF(K)  NOTMOUNT: NOT MOUNT  (hidden comment: GRM155R71E104KE14D)
IC13  USERCOMPTEXT3: TOSHIBA  (hidden comment: TC75W57FK_TE85L_F_)
IC14  VAL2: AND GATE  USERCOMPTEXT3: TOSHIBA  (hidden comment: TC7W08FK)
IC15  USERCOMPTEXT3: TOSHIBA  (hidden comment: TC75W57FK_TE85L_F_)
IC16  VAL2: AND GATE  USERCOMPTEXT3: TOSHIBA  (hidden comment: TC7W08FK)
IC17  VAL2: AND GATE  USERCOMPTEXT3: TOSHIBA  (hidden comment: TC7W08FK)
IC18  USERCOMPTEXT3: TOSHIBA  (hidden comment: TC75W57FK_TE85L_F_)
R128  SIZECODESMD: 1608  VALUE4: (D)  VAL1: 20k(D)  (hidden comment: ERJ3RBD2002V)
R129  SIZECODESMD: 1608  VALUE4: (D)  VAL1: 20k(D)  (hidden comment: ERJ3RBD2002V)
R130  SIZECODESMD: 1608  VALUE4: (D)  VAL1: 30k(D)  (hidden comment: ERJ3RBD3002V)
R131  SIZECODESMD: 1608  VALUE4: (D)  VAL1: 30k(D)  (hidden comment: ERJ3RBD3002V)
R132  SIZECODESMD: 1608  VALUE4: (D)  VAL1: 30k(D)  (hidden comment: ERJ3RBD3002V)
R133  SIZECODESMD: 1608  VALUE4: (D)  VAL1: 30k(D)  (hidden comment: ERJ3RBD3002V)
R134  SIZECODESMD: 1608  VALUE4: (D)  VAL1: 20k(D)  (hidden comment: ERJ3RBD2002V)
R135  SIZECODESMD: 1608  VALUE4: (D)  VAL1: 20k(D)  (hidden comment: ERJ3RBD2002V)
R309  VAL1: 0  (hidden comment: ERJ2GE0R00X)
R310  VAL1: 0  (hidden comment: ERJ2GE0R00X)
R311  VAL1: 0  (hidden comment: ERJ2GE0R00X)
U?#9  DATE: 2023/03/24  TITLE: Multi Level Inverter using MOSFET  REVISION: 01  SHEETNUMBER: 9/10  FUNCTION: Over Current Sensing  DRAWINGNUMBER: RD208-SCHEMATIC-01  (hidden comment: WAKU_DEF100)

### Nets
GND_D: C90.2 C91.2 C92.2 C93.2 C94.2 C95.2 C139.2 C140.2 C141.2 IC13.4(VSS) IC14.4(GND) IC15.4(VSS) IC16.4(GND) IC16.5(2A) IC16.6(2B) IC17.4(GND) IC18.4(VSS) R134.2 R135.2  [also labelled SIG24, SIG26, SIG27, SIG28, SIG33, SIG34, SIG35, SIG39, SIG41, SIG42]  [project net SIG10]
SIG22: R128.1 R129.1  [also labelled VP_3R3_PRH_D]  [project net SIG107]
SIG29: C90.1 C91.1 C92.1 C93.1 C94.1 C95.1 IC13.8(VDD) IC14.8(VCC) IC15.8(VDD) IC16.8(VCC) IC17.8(VCC) IC18.8(VDD)  [also labelled SIG31, SIG37, VP_5R0_PRH_D]  [project net SIG104]
ILIM_H: IC13.3(INA+) IC15.3(INA+) IC18.3(INA+) R129.2 R131.1 ; off-sheet ILIM_H
ILIM_L: IC13.6(INB-) IC15.6(INB-) IC18.6(INB-) R132.2 R134.1 ; off-sheet ILIM_L
ISEN_U: R309.2 ; off-sheet ISEN_U
ISEN_U_FLT: C139.1 IC13.2(INA-) IC13.5(INB+) R309.1
ISEN_V_FLT: C140.1 IC15.2(INA-) IC15.5(INB+) R310.1
ISEN_W: R311.2 ; off-sheet ISEN_W
ISEN_W_FLT: C141.1 IC18.2(INA-) IC18.5(INB+) R311.1
MCU_EMG: IC16.7(1Y) ; off-sheet MCU_EMG
N15775892: R130.2 R132.1
N15776035: R128.2 R130.1
OC_U: IC14.7(1Y) IC17.1(1A)
OC_U_N: IC13.7(OUTB) IC14.2(1B)
OC_U_P: IC13.1(OUTA) IC14.1(1A)
OC_UV: IC16.1(1A) IC17.7(1Y)
OC_V: IC14.3(2Y) IC17.2(1B)
OC_V_N: IC14.6(2B) IC15.7(OUTB)
OC_V_P: IC14.5(2A) IC15.1(OUTA)
OC_W: IC16.2(1B) IC17.3(2Y)
OC_W_N: IC17.6(2B) IC18.7(OUTB)
OC_W_P: IC17.5(2A) IC18.1(OUTA)
SIG21: R133.2 R135.1
SIG23: R131.2 R133.1
SIG233: R310.2 ; off-sheet ISEN_V  [also labelled ISEN_V]

Not connected (* = marked no-connect by the designer): IC16 3(2Y)

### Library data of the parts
C90-C95 = GRM155R71E104KE14D: MANUFACTURER: MURATA; ITEM: CAP Ceramic; SIZECODESMD: 1005; TIME: 08:44:45; UPDATEUSER: t5459927; SAVECOUNT: 1; OriginalSymbolOrigin: (0,0); INSTANCENAME: INS15829710
C139-C141 = GRM155R71E104KE14D: MANUFACTURER: MURATA; ITEM: CAP Ceramic; SIZECODESMD: 1005; TIME: 08:44:45; UPDATEUSER: t5459927; SAVECOUNT: 1; OriginalSymbolOrigin: (0,0); INSTANCENAME: INS17203421
IC13 IC15 IC18 = TC75W57FK_TE85L_F_: ITEM: IC Comparator; VAL2: COMPARATOR; VAL1: TC75W57FK(TE85L,F); TIME: 08:44:45; UPDATEUSER: PS4_common_PC; UPDATETIME: 11:17:59; SAVECOUNT: 2; SAVEAREA0: -66604,-47529,81816,20099; OriginalSymbolOrigin: (0,0)
IC14 IC17 = TC7W08FK: ITEM: IC Logic; TIME: 08:44:45; UPDATEUSER: t5459927; SAVECOUNT: 1; SAVEAREA0: -18404,-33681,30128,1847; OriginalSymbolOrigin: (0,0); INSTANCENAME: INS15825073
IC16 = TC7W08FK: ITEM: IC Logic; TIME: 08:44:45; UPDATEUSER: t5459927; SAVECOUNT: 1; SAVEAREA0: -18404,-33681,30128,1847; OriginalSymbolOrigin: (0,0); INSTANCENAME: INS15824931
R128 R129 = ERJ3RBD2002V: MANUFACTURER: Panasonic; ITEM: Register; VAL2: 100mW; TIME: 08:44:45; UPDATEUSER: t5459927; SAVECOUNT: 1; OriginalSymbolOrigin: (0,0); INSTANCENAME: INS17170385
R130 R131 = ERJ3RBD3002V: MANUFACTURER: Panasonic; ITEM: Register; VAL2: 100mW; TIME: 08:44:45; UPDATEUSER: t5459927; SAVECOUNT: 1; OriginalSymbolOrigin: (0,0); INSTANCENAME: INS17170440
R132 R133 = ERJ3RBD3002V: MANUFACTURER: Panasonic; ITEM: Register; VAL2: 100mW; TIME: 08:44:45; UPDATEUSER: t5459927; SAVECOUNT: 1; OriginalSymbolOrigin: (0,0); INSTANCENAME: INS17170452
R134 R135 = ERJ3RBD2002V: MANUFACTURER: Panasonic; ITEM: Register; VAL2: 100mW; TIME: 08:44:45; UPDATEUSER: t5459927; SAVECOUNT: 1; OriginalSymbolOrigin: (0,0); INSTANCENAME: INS17170397
R309-R311 = ERJ2GE0R00X: MANUFACTURER: Panasonic; ITEM: Register; VAL2: 1/10W; SIZECODESMD: 1005; TIME: 08:44:45; UPDATEUSER: t5459927; SAVECOUNT: 1; OriginalSymbolOrigin: (0,0); INSTANCENAME: INS17203406
U?#9 = WAKU_DEF100: PLOTTIME: HH:MM; SAVEAREA0: 185750,-43960,448537,75779; TIME: 14:30:25; UPDATEUSER: PS4_common_PC; UPDATETIME: 08:26:12; SAVECOUNT: 8; OriginalSymbolOrigin: (10160,284480)

## Sheet 10.SchDoc
size 420 x 297 mm
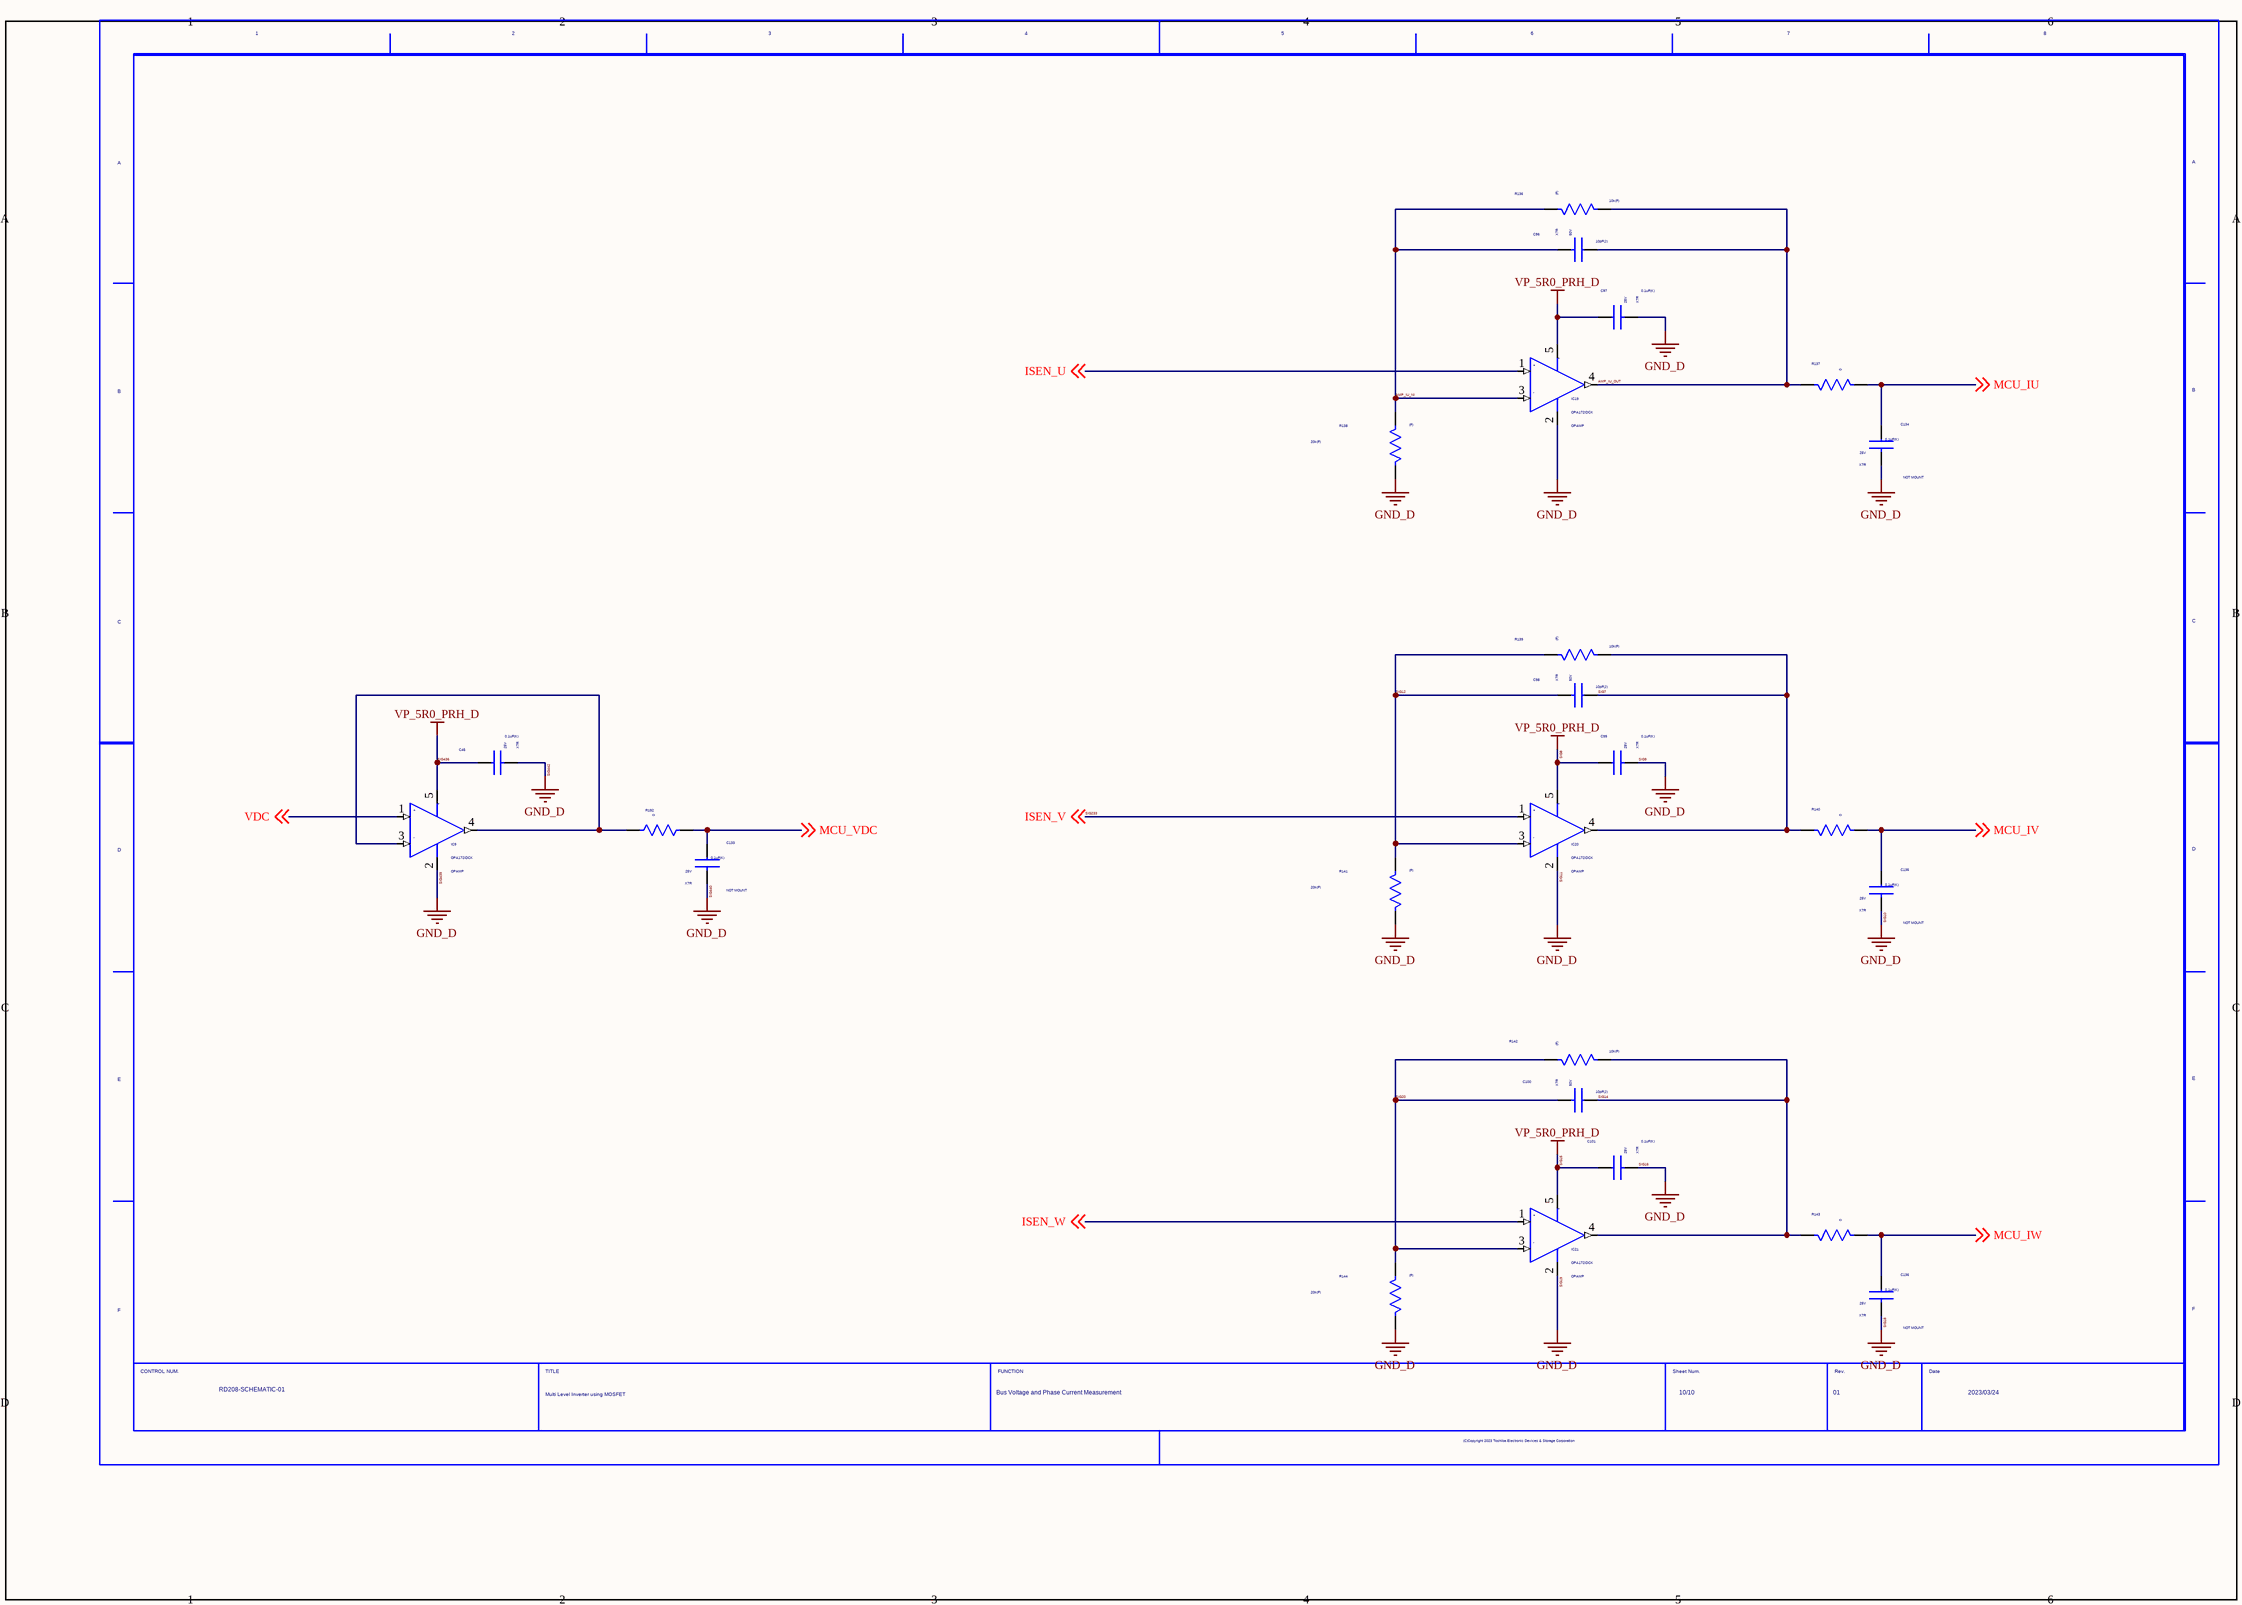
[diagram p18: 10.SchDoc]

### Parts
(Parts that share a designator on the sheet are numbered #1, #2 ... from top to bottom, then left to right.)
C45  VAL2: 25V  VALUE4: X7R  VAL1: 0.1uF(K)  (hidden comment: GRM155R71E104KE14D)
C96  VAL2: 50V  VALUE4: X7R  VAL1: 10pF(J)  (hidden comment: GRM1555C1H100RA01D)
C97  VAL2: 25V  VALUE4: X7R  VAL1: 0.1uF(K)  (hidden comment: GRM155R71E104KE14D)
C98  VAL2: 50V  VALUE4: X7R  VAL1: 10pF(J)  (hidden comment: GRM1555C1H100RA01D)
C99  VAL2: 25V  VALUE4: X7R  VAL1: 0.1uF(K)  (hidden comment: GRM155R71E104KE14D)
C100  VAL2: 50V  VALUE4: X7R  VAL1: 10pF(J)  (hidden comment: GRM1555C1H100RA01D)
C101  VAL2: 25V  VALUE4: X7R  VAL1: 0.1uF(K)  (hidden comment: GRM155R71E104KE14D)
C133  VAL2: 25V  VALUE4: X7R  VAL1: 0.1uF(K)  NOTMOUNT: NOT MOUNT  (hidden comment: GRM155R71E104KE14D)
C134  VAL2: 25V  VALUE4: X7R  VAL1: 0.1uF(K)  NOTMOUNT: NOT MOUNT  (hidden comment: GRM155R71E104KE14D)
C135  VAL2: 25V  VALUE4: X7R  VAL1: 0.1uF(K)  NOTMOUNT: NOT MOUNT  (hidden comment: GRM155R71E104KE14D)
C136  VAL2: 25V  VALUE4: X7R  VAL1: 0.1uF(K)  NOTMOUNT: NOT MOUNT  (hidden comment: GRM155R71E104KE14D)
IC9  VAL2: OPAMP  VAL1: OPA172IDCK  (hidden comment: OPA172IDCKT)
IC19  VAL2: OPAMP  VAL1: OPA172IDCK  (hidden comment: OPA172IDCKT)
IC20  VAL2: OPAMP  VAL1: OPA172IDCK  (hidden comment: OPA172IDCKT)
IC21  VAL2: OPAMP  VAL1: OPA172IDCK  (hidden comment: OPA172IDCKT)
R136  VALUE4: (F)  VAL1: 10k(F)  (hidden comment: ERJ2RKF1002X)
R137  VAL1: 0  (hidden comment: ERJ2GE0R00X)
R138  VALUE4: (F)  VAL1: 20k(F)  (hidden comment: ERJ2RKF2002X)
R139  VALUE4: (F)  VAL1: 10k(F)  (hidden comment: ERJ2RKF1002X)
R140  VAL1: 0  (hidden comment: ERJ2GE0R00X)
R141  VALUE4: (F)  VAL1: 20k(F)  (hidden comment: ERJ2RKF2002X)
R142  VALUE4: (F)  VAL1: 10k(F)  (hidden comment: ERJ2RKF1002X)
R143  VAL1: 0  (hidden comment: ERJ2GE0R00X)
R144  VALUE4: (F)  VAL1: 20k(F)  (hidden comment: ERJ2RKF2002X)
R192  VAL1: 0  (hidden comment: ERJ2GE0R00X)
U?#10  DATE: 2023/03/24  TITLE: Multi Level Inverter using MOSFET  REVISION: 01  SHEETNUMBER: 10/10  DRAWINGNUMBER: RD208-SCHEMATIC-01  FUNCTION: Bus Voltage and Phase Current Measurement  (hidden comment: WAKU_DEF100)

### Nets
SIG10: C45.2 C97.2 C99.2 C101.2 C133.2 C134.2 C135.2 C136.2 IC9.2(-V) IC19.2(-V) IC20.2(-V) IC21.2(-V) R138.1 R141.1 R144.1  [also labelled GND_D, SIG11, SIG16, SIG18, SIG19, SIG439, SIG440, SIG442, SIG9]
SIG15: C45.1 C97.1 C99.1 C101.1 IC9.5(+V) IC19.5(+V) IC20.5(+V) IC21.5(+V)  [also labelled SIG436, SIG8, VP_5R0_PRH_D]  [project net SIG104]
AMP_IU_NI: C96.2 IC19.3(-IN) R136.2 R138.2
AMP_IU_OUT: C96.1 IC19.4(OUT) R136.1 R137.2
ISEN_U: IC19.1(+IN) ; off-sheet ISEN_U
ISEN_W: IC21.1(+IN) ; off-sheet ISEN_W
MCU_IU: C134.1 R137.1 ; off-sheet MCU_IU
MCU_IV: C135.1 R140.1 ; off-sheet MCU_IV
MCU_IW: C136.1 R143.1 ; off-sheet MCU_IW
MCU_VDC: C133.1 R192.2 ; off-sheet MCU_VDC
SIG7: C98.1 IC20.4(OUT) R139.1 R140.2
SIG12: C98.2 IC20.3(-IN) R139.2 R141.2
SIG14: C100.1 IC21.4(OUT) R142.1 R143.2
SIG20: C100.2 IC21.3(-IN) R142.2 R144.2
SIG233: IC20.1(+IN) ; off-sheet ISEN_V  [also labelled ISEN_V]
SIG438: IC9.3(-IN) IC9.4(OUT) R192.1
VDC: IC9.1(+IN) ; off-sheet VDC

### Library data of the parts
C45 = GRM155R71E104KE14D: MANUFACTURER: MURATA; ITEM: CAP Ceramic; SIZECODESMD: 1005; TIME: 08:44:45; UPDATEUSER: t5459927; SAVECOUNT: 1; OriginalSymbolOrigin: (0,0); INSTANCENAME: INS15923208
C96 C98 C100 = GRM1555C1H100RA01D: MANUFACTURER: MURATA; ITEM: CAP Ceramic; SIZECODESMD: 1005; TIME: 08:44:45; UPDATEUSER: t5459927; SAVECOUNT: 1; OriginalSymbolOrigin: (0,0); INSTANCENAME: INS15880882
C97 C99 C101 = GRM155R71E104KE14D: MANUFACTURER: MURATA; ITEM: CAP Ceramic; SIZECODESMD: 1005; TIME: 08:44:45; UPDATEUSER: t5459927; SAVECOUNT: 1; OriginalSymbolOrigin: (0,0); INSTANCENAME: INS15883585
C133 = GRM155R71E104KE14D: MANUFACTURER: MURATA; ITEM: CAP Ceramic; SIZECODESMD: 1005; TIME: 08:44:45; UPDATEUSER: t5459927; SAVECOUNT: 1; OriginalSymbolOrigin: (0,0); INSTANCENAME: INS17202360
C134-C136 = GRM155R71E104KE14D: MANUFACTURER: MURATA; ITEM: CAP Ceramic; SIZECODESMD: 1005; TIME: 08:44:45; UPDATEUSER: t5459927; SAVECOUNT: 1; OriginalSymbolOrigin: (0,0); INSTANCENAME: INS17202303
IC9 = OPA172IDCKT: MANUFACTURER: TI; ITEM: Operational Amplifier; ORDER: 0; TIME: 08:44:45; UPDATEUSER: t5459927; SAVECOUNT: 1; OriginalSymbolOrigin: (0,0); INSTANCENAME: INS16694428
IC19-IC21 = OPA172IDCKT: MANUFACTURER: TI; ITEM: Operational Amplifier; ORDER: 0; TIME: 08:44:45; UPDATEUSER: t5459927; SAVECOUNT: 1; OriginalSymbolOrigin: (0,0); INSTANCENAME: INS16693220
R136 R139 R142 = ERJ2RKF1002X: MANUFACTURER: Panasonic; ITEM: Register; VAL2: 100mW; SIZECODESMD: 1005; TIME: 08:44:45; UPDATEUSER: t5459927; SAVECOUNT: 1; OriginalSymbolOrigin: (0,0); INSTANCENAME: INS16030382
R137 R140 R143 = ERJ2GE0R00X: MANUFACTURER: Panasonic; ITEM: Register; VAL2: 1/10W; SIZECODESMD: 1005; TIME: 08:44:45; UPDATEUSER: t5459927; SAVECOUNT: 1; OriginalSymbolOrigin: (0,0); INSTANCENAME: INS17202155
R138 R141 R144 = ERJ2RKF2002X: MANUFACTURER: Panasonic; ITEM: Register; VAL2: 100mW; SIZECODESMD: 1005; TIME: 08:44:45; UPDATEUSER: t5459927; SAVECOUNT: 1; OriginalSymbolOrigin: (0,0); INSTANCENAME: INS16030446
R192 = ERJ2GE0R00X: MANUFACTURER: Panasonic; ITEM: Register; VAL2: 1/10W; SIZECODESMD: 1005; TIME: 08:44:45; UPDATEUSER: t5459927; SAVECOUNT: 1; OriginalSymbolOrigin: (0,0); INSTANCENAME: INS16109810
U?#10 = WAKU_DEF100: PLOTTIME: HH:MM; SAVEAREA0: 185750,-43960,448537,75779; TIME: 14:30:25; UPDATEUSER: PS4_common_PC; UPDATETIME: 08:26:28; SAVECOUNT: 8; OriginalSymbolOrigin: (10160,284480)

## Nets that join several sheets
SIG1: 1 (12 pins), 6 (8 pins), 7 (6 pins), 8 (6 pins)
SIG10: 3 (8 pins), 4 (25 pins), 5 (28 pins), 6 (21 pins), 7 (19 pins), 8 (19 pins), 9 (19 pins), 10 (15 pins)
SIG104: 3 (9 pins), 4 (22 pins), 6 (8 pins), 7 (8 pins), 8 (8 pins), 9 (12 pins), 10 (8 pins)
SIG107: 3 (C25.1 IC4.5 TP7.1), 4 (29 pins), 5 (17 pins), 6 (C61.1 IC10.8 R289.2), 7 (C75.1 IC11.8 R291.2), 8 (C89.1 IC12.8 R293.2), 9 (R128.1 R129.1)
SIG119: 2 (C17.1 D7.K R301.1 R302.1), 6 (D14.A D16.A D18.A R86.2)
SIG200: 1 (41 pins), 2 (18 pins), 6 (8 pins), 7 (C71.2 IC11.3 IC11.4 R202.2), 8 (C84.2 IC12.3 IC12.4 R206.2)
SIG235: 2 (C20.1 D11.K R307.1 R308.1), 6 (D20.A D22.A D24.A R94.2), 7 (D32.A D34.A D36.A R110.2), 8 (D44.A D46.A D48.A R126.2)
SIG445: 2 (C18.2 R303.2 R304.2 T2.12), 7 (13 pins)
SIG501: 3 (C30.1 IC5.5 TP8.1), 5 (5 pins)
V_UL: 2 (C17.2 R301.2 R302.2 T2.15), 6 (13 pins)
V_VH: 2 (C18.1 D8.K R303.1 R304.1), 7 (D26.A D28.A D30.A R103.2)
V_WH: 2 (C19.1 D9.K R305.1 R306.1), 8 (D38.A D40.A D42.A R118.2)
V_WL: 2 (C19.2 R305.2 R306.2 T2.9), 8 (13 pins)
VP_15R0_INV_ISO: 1 (R20.2 R21.2 R23.2 R25.2), 2 (5 pins)
CP_MODE: 4 (IC6.6 R52.2), 5 (IC7.7)
CP_RESET: 4 (IC6.7 R53.2), 5 (IC7.8)
CP_RSV1: 4 (IC6.8 R54.2), 5 (IC7.9)
CP_RSV2: 4 (IC6.9 R55.2), 5 (IC7.10)
CP_RSV3: 4 (IC8.8 R72.2), 5 (IC7.60)
CP_RSV4: 4 (IC8.9 R73.2), 5 (IC7.61)
CP_TCK: 4 (IC6.3 R49.2), 5 (IC7.48 R75.2)
CP_TDI: 4 (IC6.4 R50.2), 5 (IC7.45 R78.2)
CP_TDO: 4 (IC6.2 R48.2), 5 (IC7.83 R77.2)
CP_TMS: 4 (IC6.5 R51.2), 5 (IC7.47 R76.2)
CP_UH: 4 (IC8.2 R66.2), 5 (IC7.30)
CP_UL: 4 (IC8.3 R67.2), 5 (IC7.32)
CP_VH: 4 (IC8.4 R68.2), 5 (IC7.33)
CP_VL: 4 (IC8.5 R69.2), 5 (IC7.34)
CP_WH: 4 (IC8.6 R70.2), 5 (IC7.35)
CP_WL: 4 (IC8.7 R71.2), 5 (IC7.36)
ISEN_U: 6 (IC10.7), 9 (R309.2), 10 (IC19.1)
ISEN_W: 8 (IC12.7), 9 (R311.2), 10 (IC21.1)
MCU_EMG: 4 (CN3.25), 9 (IC16.7)
MCU_IU: 4 (CN3.36), 10 (C134.1 R137.1)
MCU_IV: 4 (CN3.38), 10 (C135.1 R140.1)
MCU_IW: 4 (CN3.40), 10 (C136.1 R143.1)
MCU_VDC: 4 (CN3.26), 10 (C133.1 R192.2)
OUT_V: 6 (CN5.2), 7 (DR2.2)
OUT_W: 6 (CN5.3), 8 (DR3.2)
SIG233: 7 (IC11.7), 9 (R310.2), 10 (IC20.1)
SIG462: 5 (IC7.94), 8 (Q46.1 R334.1 TP54.1)
SIG463: 5 (IC7.95), 8 (Q48.1 R335.1 TP55.1)
SIG464: 5 (IC7.96), 8 (Q50.1 R336.1 TP56.1)
SIG465: 5 (IC7.93), 8 (Q44.1 R333.1 TP53.1)
SIG469: 5 (IC7.90), 8 (Q38.1 R330.1 TP50.1)
SIG474: 5 (IC7.92), 8 (Q42.1 R332.1 TP52.1)
SIG475: 5 (IC7.91), 8 (Q40.1 R331.1 TP51.1)
SIG477: 5 (IC7.89), 8 (Q36.1 R329.1 TP49.1)
SIG479: 5 (IC7.66), 6 (Q6.1 R314.1 TP18.1)
SIG480: 5 (IC7.65), 6 (Q4.1 R313.1 TP17.1)
SIG481: 5 (IC7.73), 6 (Q18.1 R320.1 TP24.1)
SIG485: 5 (IC7.82), 7 (Q32.1 R327.1 TP39.1)
SIG487: 5 (IC7.85), 7 (Q34.1 R328.1 TP40.1)
SIG493: 5 (IC7.81), 7 (Q30.1 R326.1 TP38.1)
SIG495: 5 (IC7.77), 7 (Q22.1 R322.1 TP34.1)
SIG497: 5 (IC7.78), 7 (Q24.1 R323.1 TP35.1)
SIG498: 5 (IC7.80), 7 (Q28.1 R325.1 TP37.1)
SIG503: 5 (IC7.76), 7 (Q20.1 R321.1 TP33.1)
SIG504: 5 (IC7.79), 7 (Q26.1 R324.1 TP36.1)
SIG509: 5 (IC7.70), 6 (Q12.1 R317.1 TP21.1)
SIG513: 5 (IC7.71), 6 (Q14.1 R318.1 TP22.1)
SIG514: 5 (IC7.72), 6 (Q16.1 R319.1 TP23.1)
SIG521: 5 (IC7.68), 6 (Q10.1 R316.1 TP20.1)
SIG522: 5 (IC7.67), 6 (Q8.1 R315.1 TP19.1)
VDC: 1 (C11.1 C130.1 R10.2 R15.1), 10 (IC9.1)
